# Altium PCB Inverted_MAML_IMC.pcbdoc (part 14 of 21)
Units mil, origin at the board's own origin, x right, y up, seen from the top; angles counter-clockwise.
Board outline 7677.1 x 6771.6 mil, 6 copper layers (Top Layer, Inner1, Inner2, Inner3, Inner4, Bottom Layer), stack 60.7 mil thick; 2732 components, 1531 nets, 7765 pads, 3705 vias.
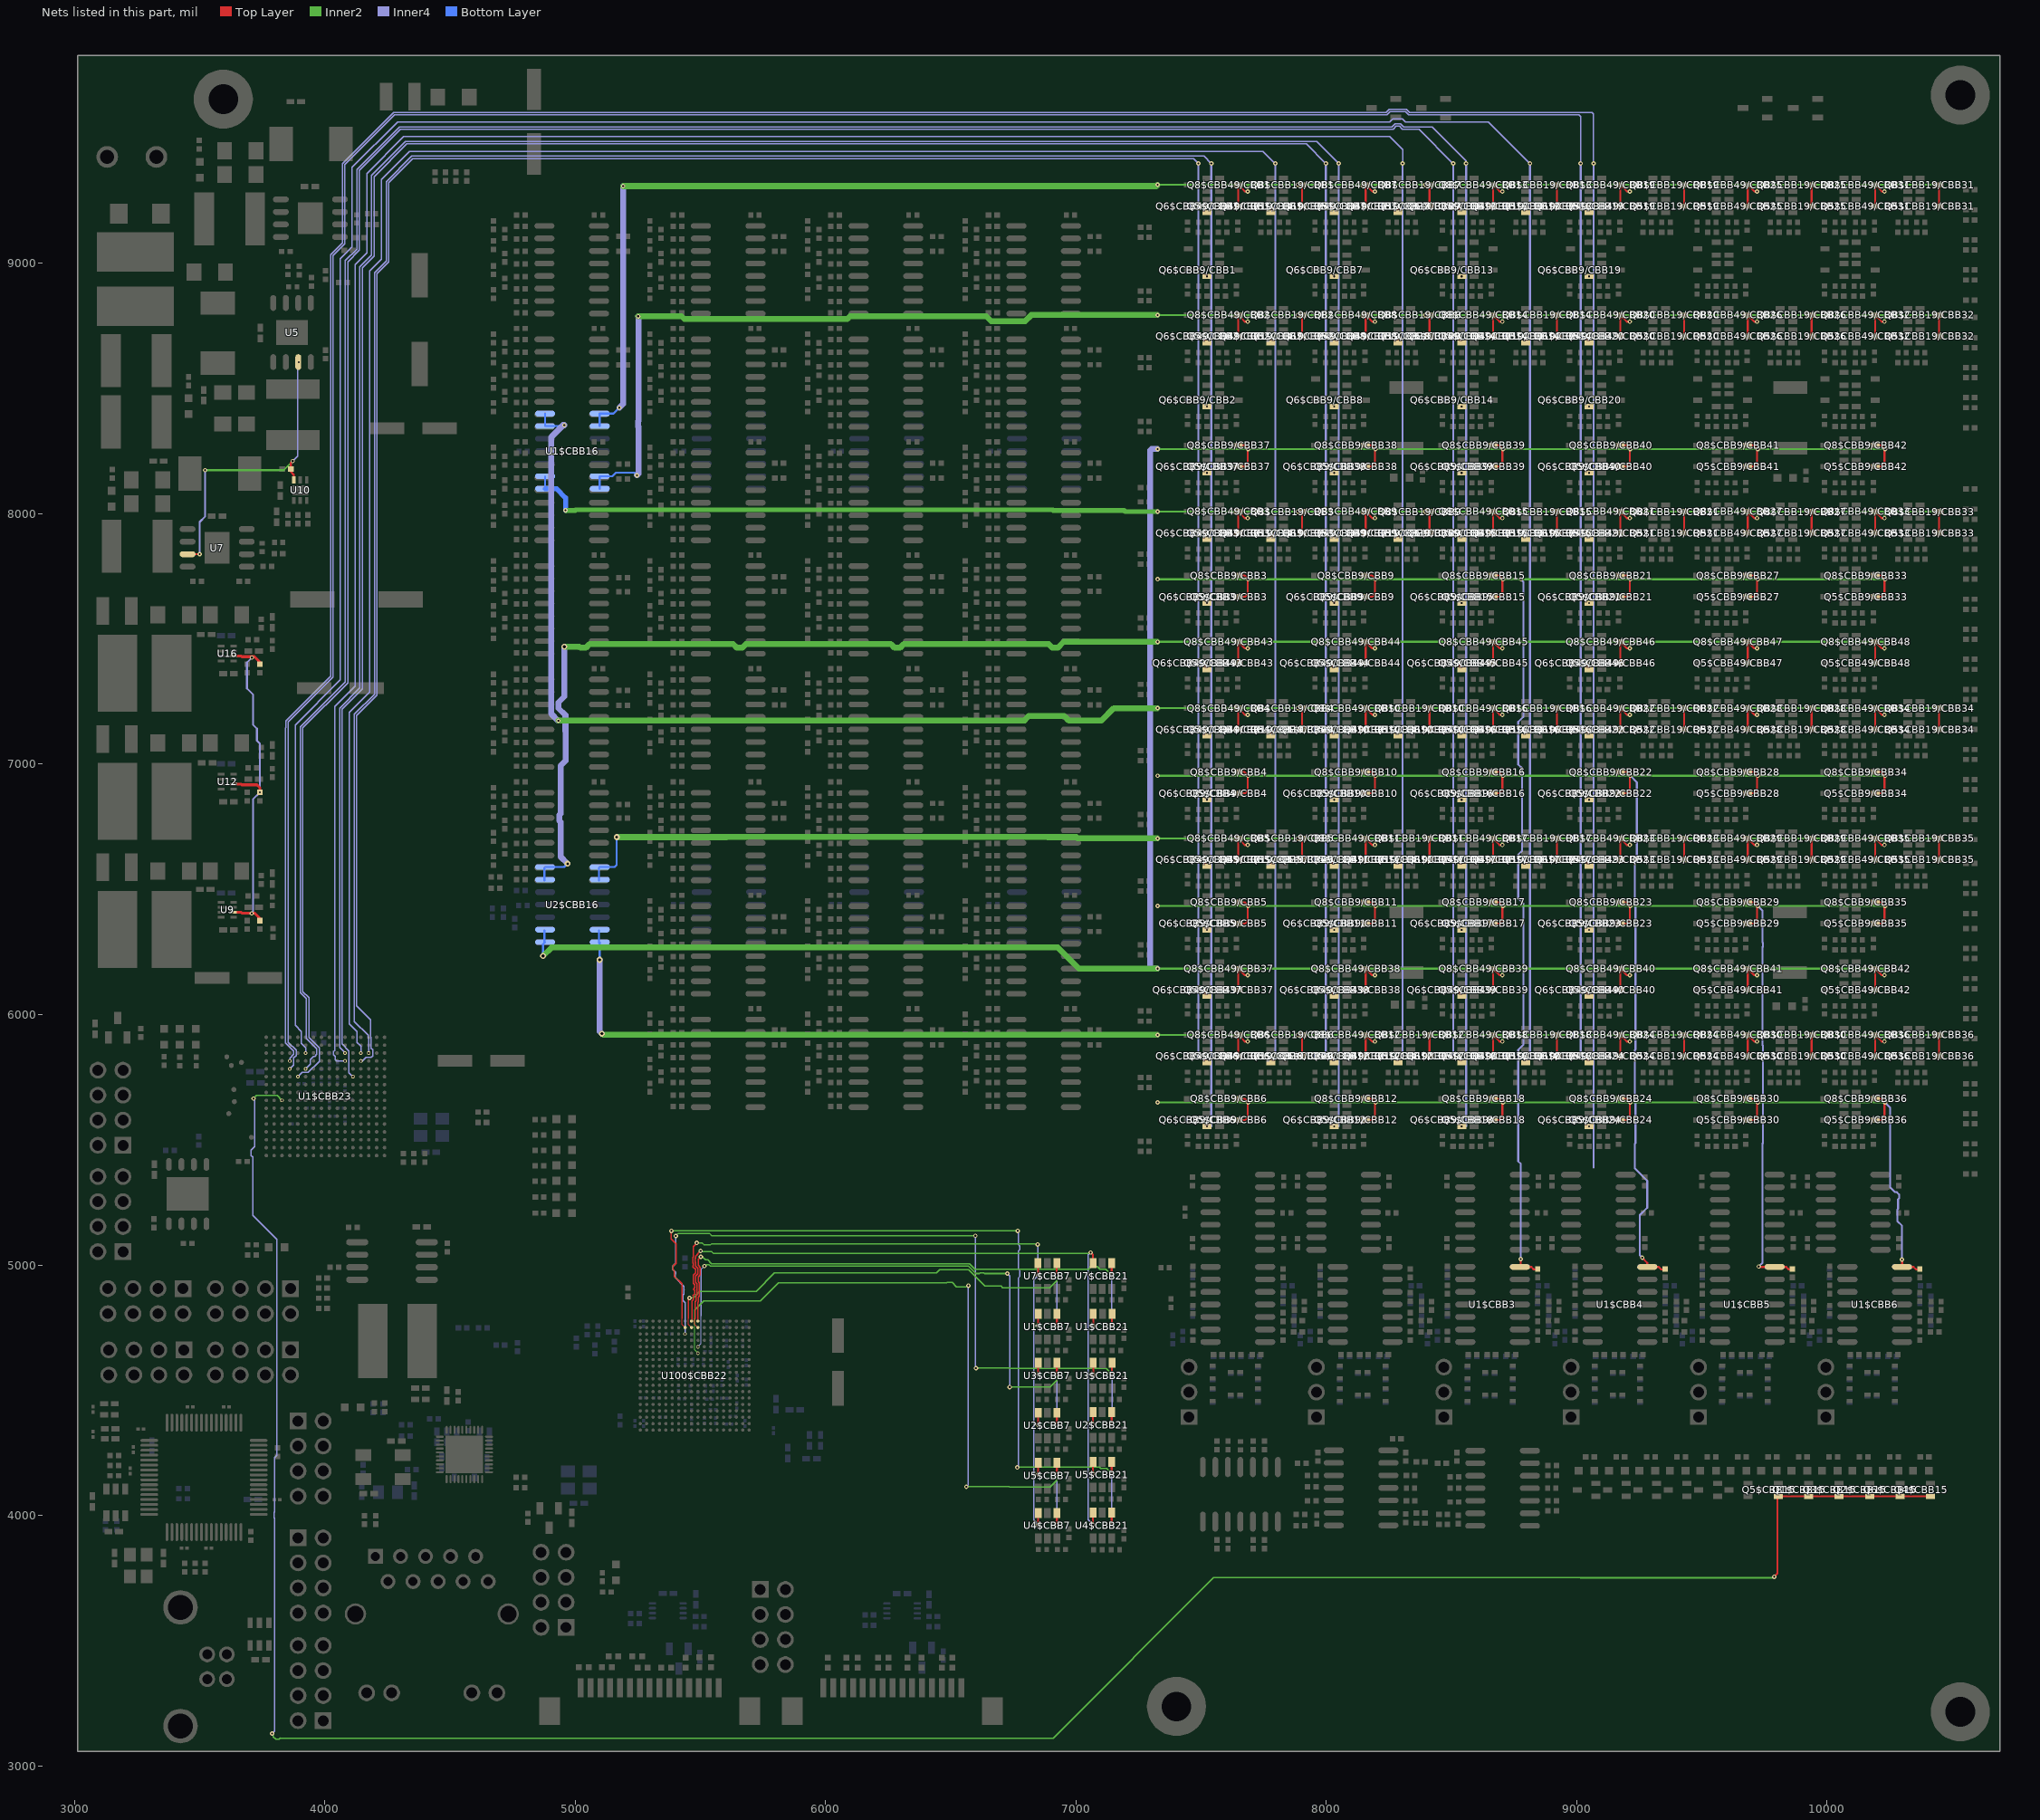
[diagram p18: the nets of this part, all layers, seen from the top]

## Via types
v1: diameter 17.7, hole 7.9, Top Layer to Bottom Layer, 3373 vias
v2: diameter 13.8, hole 7.9, Top Layer to Bottom Layer, 287 vias
v3: diameter 23.6, hole 11.8, Top Layer to Bottom Layer, 45 vias

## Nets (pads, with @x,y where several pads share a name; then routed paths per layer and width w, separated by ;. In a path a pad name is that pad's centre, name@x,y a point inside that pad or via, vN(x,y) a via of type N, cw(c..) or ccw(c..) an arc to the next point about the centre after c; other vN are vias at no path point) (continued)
ACT(4)_D_ROW3: Q5$CBB9/CBB3.3 Q5$CBB9/CBB9.3 Q5$CBB9/CBB15.3 Q5$CBB9/CBB21.3 Q5$CBB9/CBB27.3 Q5$CBB9/CBB33.3 Q8$CBB9/CBB3.3 Q8$CBB9/CBB9.3 Q8$CBB9/CBB15.3 Q8$CBB9/CBB21.3 Q8$CBB9/CBB27.3 Q8$CBB9/CBB33.3 R14$CBB3.2 U1$CBB3.14 | length 6663.9
  Top Layer w7.9: Q5$CBB9/CBB3.3@7648.6,7668.7 7676.2,7668.7 7686.2,7678.7 v1@7686.2,7738.7 ; Q8$CBB9/CBB3.3@7648.6,7753.7 7673.7,7753.7 v1(7688.7,7738.7) ; Q5$CBB9/CBB9.3@8157.3,7668.7 8184.9,7668.7 8194.9,7678.7 v1@8194.9,7738.7 ; Q8$CBB9/CBB9.3@8157.3,7753.7 8182.4,7753.7 v1(8197.4,7738.7) ; Q5$CBB9/CBB15.3@8666,7668.7 8693.6,7668.7 8703.6,7678.7 v1@8703.6,7738.7 ; Q8$CBB9/CBB15.3@8666,7753.7 8691.1,7753.7 v1(8706.1,7738.7) ; v1(8777.1,5023.7) 8777.1,4995.7 U1$CBB3.14@8773.5,4992.2 8819.5,4992.2 8829.5,4982.2 8842.5,4982.2 R14$CBB3.2@8844.5,4984.2 ; Q5$CBB9/CBB21.3@9174.7,7668.7 9202.3,7668.7 9212.3,7678.7 v1@9212.3,7738.7 ; Q8$CBB9/CBB21.3@9174.7,7753.7 9199.8,7753.7 v1(9214.8,7738.7) ; Q5$CBB9/CBB27.3@9683.4,7668.7 9711,7668.7 9721,7678.7 v1@9721,7738.7 ; Q8$CBB9/CBB27.3@9683.4,7753.7 9708.5,7753.7 v1(9723.5,7738.7) ; Q5$CBB9/CBB33.3@10192.1,7668.7 10219.7,7668.7 10229.7,7678.7 v1@10229.7,7738.7 ; Q8$CBB9/CBB33.3@10192.1,7753.7 10217.2,7753.7 v1(10232.2,7738.7)
  Inner2 w7.9: v1(7326.2,7738.7) v1(7688.7,7738.7) v1(8197.4,7738.7) v1(8706.1,7738.7) v1(8777.6,7738.7) v1(9214.8,7738.7) v1(9723.5,7738.7) v1(10232.2,7738.7)
  Inner4 w7.9: v1(8777.1,5023.7) 8777.1,5403.7 8767.1,5413.7 8767.1,5858.7 8787.1,5878.7 8787.1,6443.7 8767.1,6463.7 8767.1,6638.7 8782.1,6653.7 8782.1,6983.7 8767.1,6998.7 8767.1,7168.7 8787.1,7188.7 8787.1,7728.7 v1@8777.1,7738.7
ACT(4)_D_ROW4: Q5$CBB9/CBB4.3 Q5$CBB9/CBB10.3 Q5$CBB9/CBB16.3 Q5$CBB9/CBB22.3 Q5$CBB9/CBB28.3 Q5$CBB9/CBB34.3 Q8$CBB9/CBB4.3 Q8$CBB9/CBB10.3 Q8$CBB9/CBB16.3 Q8$CBB9/CBB22.3 Q8$CBB9/CBB28.3 Q8$CBB9/CBB34.3 R14$CBB4.2 U1$CBB4.14 | length 5896.7
  Top Layer w7.9: Q5$CBB9/CBB4.3@7648.6,6883.7 7676.2,6883.7 7686.2,6893.7 v1@7686.2,6953.7 ; Q8$CBB9/CBB4.3@7648.6,6968.7 7673.7,6968.7 v1(7688.7,6953.7) ; Q5$CBB9/CBB10.3@8157.3,6883.7 8184.9,6883.7 8194.9,6893.7 v1@8194.9,6953.7 ; Q8$CBB9/CBB10.3@8157.3,6968.7 8182.4,6968.7 v1(8197.4,6953.7) ; Q5$CBB9/CBB16.3@8666,6883.7 8693.6,6883.7 8703.6,6893.7 v1@8703.6,6953.7 ; Q8$CBB9/CBB16.3@8666,6968.7 8691.1,6968.7 v1(8706.1,6953.7) ; Q5$CBB9/CBB22.3@9174.7,6883.7 9202.3,6883.7 9212.3,6893.7 v1@9212.3,6953.7 ; Q8$CBB9/CBB22.3@9174.7,6968.7 9199.8,6968.7 v1(9214.8,6953.7) ; v1(9262.1,5028.7) 9282.3,5008.6 U1$CBB4.14@9282.3,4992.2 9328.2,4992.2 9338.2,4982.2 9351.2,4982.2 R14$CBB4.2@9353.2,4984.2 ; Q5$CBB9/CBB28.3@9683.4,6883.7 9711,6883.7 9721,6893.7 v1@9721,6953.7 ; Q8$CBB9/CBB28.3@9683.4,6968.7 9708.5,6968.7 v1(9723.5,6953.7) ; Q5$CBB9/CBB34.3@10192.1,6883.7 10219.7,6883.7 10229.7,6893.7 v1@10229.7,6953.7 ; Q8$CBB9/CBB34.3@10192.1,6968.7 10217.2,6968.7 v1(10232.2,6953.7)
  Inner2 w7.9: v1(7326.2,6953.7) v1(7688.7,6953.7) v1(8197.4,6953.7) v1(8706.1,6953.7) v1(9214.8,6953.7) v1(9723.5,6953.7) v1(10232.2,6953.7)
  Inner4 w7.9: v1(9214.8,6953.7) 9240.7,6927.8 9240.7,6632.3 9232.1,6623.7 9232.1,6441.5 9235.1,6438.6 9235.1,5861.4 9232.1,5858.4 9232.1,5656.5 9235.1,5653.6 9235.1,5486.4 9232.1,5483.4 9232.1,5386.5 9282.1,5336.5 9282.1,5228.7 9252.1,5198.7 9252.1,5038.7 v1(9262.1,5028.7)
ACT(4)_D_ROW5: Q5$CBB9/CBB5.3 Q5$CBB9/CBB11.3 Q5$CBB9/CBB17.3 Q5$CBB9/CBB23.3 Q5$CBB9/CBB29.3 Q5$CBB9/CBB35.3 Q8$CBB9/CBB5.3 Q8$CBB9/CBB11.3 Q8$CBB9/CBB17.3 Q8$CBB9/CBB23.3 Q8$CBB9/CBB29.3 Q8$CBB9/CBB35.3 R14$CBB5.2 U1$CBB5.14 | length 5391.4
  Top Layer w7.9: Q5$CBB9/CBB5.3@7648.6,6363.7 7676.2,6363.7 7686.2,6373.7 v1@7686.2,6433.7 ; Q8$CBB9/CBB5.3@7648.6,6448.7 7673.7,6448.7 v1(7688.7,6433.7) ; Q5$CBB9/CBB11.3@8157.3,6363.7 8184.9,6363.7 8194.9,6373.7 v1@8194.9,6433.7 ; Q8$CBB9/CBB11.3@8157.3,6448.7 8182.4,6448.7 v1(8197.4,6433.7) ; Q5$CBB9/CBB17.3@8666,6363.7 8693.6,6363.7 8703.6,6373.7 v1@8703.6,6433.7 ; Q8$CBB9/CBB17.3@8666,6448.7 8691.1,6448.7 v1(8706.1,6433.7) ; Q5$CBB9/CBB23.3@9174.7,6363.7 9202.3,6363.7 9212.3,6373.7 v1@9212.3,6433.7 ; Q8$CBB9/CBB23.3@9174.7,6448.7 9199.8,6448.7 v1(9214.8,6433.7) ; Q5$CBB9/CBB29.3@9683.4,6363.7 9711,6363.7 9721,6373.7 v1@9721,6433.7 ; Q8$CBB9/CBB29.3@9683.4,6448.7 9708.5,6448.7 v1(9723.5,6433.7) ; v1(9727.1,4993.7) 9728.7,4992.2 U1$CBB5.14@9791,4992.2 9836.9,4992.2 9846.9,4982.2 9859.9,4982.2 R14$CBB5.2@9861.9,4984.2 ; Q5$CBB9/CBB35.3@10192.1,6363.7 10219.7,6363.7 10229.7,6373.7 v1@10229.7,6433.7 ; Q8$CBB9/CBB35.3@10192.1,6448.7 10217.2,6448.7 v1(10232.2,6433.7)
  Inner2 w7.9: v1(7326.2,6433.7) v1(7688.7,6433.7) v1(8197.4,6433.7) v1(8706.1,6433.7) v1(9214.8,6433.7) v1(9723.5,6433.7) v1(10232.2,6433.7)
  Inner4 w7.9: v1(9723.5,6433.7) 9742.1,6415.1 9742.1,6287.8 9743.8,6286.1 9743.8,6271.4 9742.1,6269.7 9742.1,5877.8 9743.8,5876.1 9743.8,5486.4 9742.1,5484.7 9742.1,5008.7 v1(9727.1,4993.7)
ACT(4)_D_ROW6: Q5$CBB9/CBB6.3 Q5$CBB9/CBB12.3 Q5$CBB9/CBB18.3 Q5$CBB9/CBB24.3 Q5$CBB9/CBB30.3 Q5$CBB9/CBB36.3 Q8$CBB9/CBB6.3 Q8$CBB9/CBB12.3 Q8$CBB9/CBB18.3 Q8$CBB9/CBB24.3 Q8$CBB9/CBB30.3 Q8$CBB9/CBB36.3 R14$CBB6.2 U1$CBB6.14 | length 4563.1
  Top Layer w7.9: Q5$CBB9/CBB6.3@7648.6,5578.7 7676.2,5578.7 7686.2,5588.7 v1@7686.2,5648.7 ; Q8$CBB9/CBB6.3@7648.6,5663.7 7673.7,5663.7 v1(7688.7,5648.7) ; Q5$CBB9/CBB12.3@8157.3,5578.7 8184.9,5578.7 8194.9,5588.7 v1@8194.9,5648.7 ; Q8$CBB9/CBB12.3@8157.3,5663.7 8182.4,5663.7 v1(8197.4,5648.7) ; Q5$CBB9/CBB18.3@8666,5578.7 8693.6,5578.7 8703.6,5588.7 v1@8703.6,5648.7 ; Q8$CBB9/CBB18.3@8666,5663.7 8691.1,5663.7 v1(8706.1,5648.7) ; Q5$CBB9/CBB24.3@9174.7,5578.7 9202.3,5578.7 9212.3,5588.7 v1@9212.3,5648.7 ; Q8$CBB9/CBB24.3@9174.7,5663.7 9199.8,5663.7 v1(9214.8,5648.7) ; Q5$CBB9/CBB30.3@9683.4,5578.7 9711,5578.7 9721,5588.7 v1@9721,5648.7 ; Q8$CBB9/CBB30.3@9683.4,5663.7 9708.5,5663.7 v1(9723.5,5648.7) ; Q5$CBB9/CBB36.3@10192.1,5578.7 10219.7,5578.7 10229.7,5588.7 v1@10229.7,5648.7 ; Q8$CBB9/CBB36.3@10192.1,5663.7 10217.2,5663.7 v1(10232.2,5648.7) ; v1(10299.5,5021.7) 10299.7,5021.6 U1$CBB6.14@10299.7,4992.2 10345.6,4992.2 10355.6,4982.2 10368.6,4982.2 R14$CBB6.2@10370.6,4984.2
  Inner2 w7.9: v1(7326.2,5648.7) v1(7688.7,5648.7) v1(8197.4,5648.7) v1(8706.1,5648.7) v1(9214.8,5648.7) v1(9723.5,5648.7) v1(10232.2,5648.7)
  Inner4 w7.9: v1(10232.2,5648.7) 10252.1,5628.8 10252.1,5501.5 10252.5,5501.1 10252.5,5486.4 10252.1,5486 10252.1,5309.9 10270.4,5291.6 10277.4,5291.6 10287.8,5281.2 10287.8,5266.4 10283.8,5262.4 10283.8,5224.3 10280.6,5221 10280.6,5175.2 10299.6,5156.1 v1@10299.6,5023.7
ADC(45)_CONV: U1$CBB7.6 U2$CBB7.6 U3$CBB7.6 U4$CBB7.6 U5$CBB7.6 U7$CBB7.6 U100$CBB22.V10 | length 3202.2
  Top Layer w4.7: U100$CBB22.V10@5465.1,4775.7 5467.2,4777.8 5467.2,4855.7 5473.2,4861.7 5473.2,4875.1 5470.9,4877.5 5477.2,4883.8 5477.2,4897.2 5471.9,4902.6 5477.2,4907.9 5477.2,4921.3 5472.5,4926 5472.5,4944.9 5472,4945.3 5472,4960.3 5480.7,4969 5480.7,4982.4 5471.2,4991.9 5470,4991.9 5470,4994.9 5472.5,4997.4 5472.5,5006.7 5470.7,5008.5 5470.7,5030 5472.5,5031.8 5472.5,5074.2 v1(5486.4,5088.1)
  Top Layer w7.9: U7$CBB7.6@6849.2,5006.9 6849.2,4959.7 v1(6849.4,4959.5) ; U4$CBB7.6@6849.7,4009.9 6849.7,3962.7 v1(6849.9,3962.5) ; U5$CBB7.6@6849.7,4209.9 6849.7,4162.7 v1(6849.9,4162.5) ; U2$CBB7.6@6849.7,4409.9 6849.7,4362.7 v1(6849.9,4362.5) ; U3$CBB7.6@6849.7,4609.9 6849.7,4562.7 v1(6849.9,4562.5) ; U1$CBB7.6@6849.7,4804.9 6849.7,4757.7 v1(6849.9,4757.5)
  Inner2 w5.5: v1(5486.4,5088.1) 5507.9,5088.1 5514.9,5081.1 5542,5081.1 5545.6,5084.7 6845.4,5084.7 v1(6847.9,5082.1)
  Inner4 w4.7: 6831.7,4162.4 6831.9,4162.4 ; v1(6849.4,4959.5) 6831.9,4941.9 6831.9,4757.2 ; v1@6849.7,4162.7 6849.4,4162.4 6831.9,4162.4 ; v1(6849.9,3962.5) 6831.9,3980.6 6831.9,4162.4 ; v1(6849.9,4362.5) 6849.6,4362.2 6831.9,4362.2 ; v1(6849.9,4562.5) 6849.6,4562.2 6831.9,4562.2 ; v1(6849.9,4757.5) 6849.6,4757.2 6831.9,4757.2 ; 6831.9,4162.4 6831.9,4362.2 ; 6831.9,4362.2 6831.9,4562.2 ; 6831.9,4562.2 6831.9,4757.2
  Inner4 w5.5: v1(6847.9,5082.1) 6847.9,4960.9 v1(6849.4,4959.5)
ADC(45)_SCK_1_2: U1$CBB7.4 U7$CBB7.4 U100$CBB22.U10 | length 2000.1
  Top Layer w4.3: 5452.1,4785.2 5452.5,4784.8 5452.5,4762.7 U100$CBB22.U10@5465.1,4750.1
  Top Layer w4.7: 5452.1,4785.2 5452.1,4863.6 v1(5457,4868.4)
  Top Layer w7.9: U7$CBB7.4@6924,5006.9 6924,4959.7 v1(6924.2,4959.5) ; U1$CBB7.4@6924.5,4804.9 6924.5,4757.7 v1(6924.7,4757.5)
  Inner2 w4.7: v1(5457,4868.4) 5471.6,4868.4 5498.5,4895.2 5723.3,4895.2 5796.2,4968.1 6443.1,4968.1 6456.1,4981.1 6571.2,4981.1 6636.1,4916.2 6692.3,4916.2 6692.8,4915.6 6702,4915.6 6708.2,4909.4 6896.1,4909.4 6924.2,4937.5 v1(6924.2,4959.5)
  Inner4 w4.7: v1(6924.2,4959.5) 6924.2,4758.1 v1(6924.7,4757.5)
ADC(45)_SCK_3_4: U2$CBB7.4 U3$CBB7.4 U100$CBB22.P9 | length 2538.3
  Top Layer w7.9: U2$CBB7.4@6924.5,4409.9 6924.5,4362.7 v1(6924.7,4362.5) ; U3$CBB7.4@6924.5,4609.9 6924.5,4562.7 v1(6924.7,4562.5)
  Inner2 w4.7: v1(6736,4512.5) 6896.6,4512.5 6924.7,4540.6 v1(6924.7,4562.5)
  Inner2 w5.5: v1(5516.4,4995.6) 5521.1,5000.4 5535.6,5000.4 5541.1,4994.8 6571.7,4994.8 6600.9,4965.7 6615.6,4965.7 6618.2,4968.2 6631.9,4968.2 6634.5,4965.7 v1(6725.8,4965.7)
  Inner4 w3.9: v2(5490.7,4673.3) 5503.5,4686.1 5503.5,4796.2
  Inner4 w4.7: 5503.5,4796.2 5503.5,4843.2 ; v1(6924.7,4562.5) 6924.7,4361.1 v1@6925.3,4360.6
  Inner4 w5.5: 5503.5,4843.2 5502.6,4844 5502.6,4981.8 v1(5516.4,4995.6) ; v1(6725.8,4965.7) 6736,4955.5 v1(6736,4512.5)
ADC(45)_SCK_5_6: U4$CBB7.4 U5$CBB7.4 U100$CBB22.N9 | length 2824.2
  Top Layer w7.9: U4$CBB7.4@6924.5,4009.9 6924.5,3962.7 v1(6924.7,3962.5) ; U5$CBB7.4@6924.5,4209.9 6924.5,4162.7 v1(6924.7,4162.5)
  Inner2 w3.9: 5477.9,4796.2 5477.9,4660.6 v2(5490.7,4647.8)
  Inner2 w4.7: 5477.9,4796.2 5477.9,4819.6 5514.6,4856.3 5739.5,4856.3 5812.3,4929.2 6485.3,4929.2 6485.8,4929.7 6507.3,4929.7 6523.8,4913.1 6566.5,4913.1 v1(6570.8,4917.5) ; 6736,4112.5 6896.6,4112.5 6924.7,4140.6 v1(6924.7,4162.5)
  Inner2 w5.5: v1(6562.8,4114.3) 6734.2,4114.3 6736,4112.5
  Inner4 w4.7: v1(6924.7,4162.5) 6924.7,3961.1 v1@6925.3,3960.6
  Inner4 w5.5: v1(6562.8,4114.3) 6570.8,4122.4 v1(6570.8,4917.5)
ADC(49)_CONV: U1$CBB21.6 U2$CBB21.6 U3$CBB21.6 U4$CBB21.6 U5$CBB21.6 U7$CBB21.6 U100$CBB22.U9 | length 3362.5
  Top Layer w4.3: 5477.7,4785.2 5478.1,4784.8 5478.1,4762.7 U100$CBB22.U9@5490.7,4750.1
  Top Layer w4.7: 5477.7,4785.2 5478.9,4786.3 5478.9,4853.6 5482.9,4857.7 5482.9,4875.7 5486.9,4879.8 5486.9,4901.3 5485.6,4902.6 5486.9,4903.9 5486.9,4925.3 5482.2,4930.1 5482.2,4948.9 5481.8,4949.3 5481.8,4956.3 5490.4,4965 5490.4,4986.5 5482.2,4994.7 5482.2,5010.7 5480.4,5012.6 5480.4,5026 5482.2,5027.8 5482.2,5035.6 5486.4,5039.8 5486.4,5041.4 5495.9,5050.9 5496.2,5050.9 v1(5501.4,5056.2)
  Top Layer w7.9: v1(7058.7,5049.8) 7068.5,5040 U7$CBB21.6@7068.5,5006.9 ; U4$CBB21.6@7068.5,4010.7 7068.5,3963.4 v1(7068.7,3963.3) ; U5$CBB21.6@7068.5,4213.9 7068.5,4166.2 v1(7068.7,4166) ; U2$CBB21.6@7068.5,4412.2 7068.5,4364.9 v1(7068.7,4364.7) ; U3$CBB21.6@7069.7,4609.9 7069.7,4562.7 v1(7069.9,4562.5) ; U1$CBB21.6@7069.7,4804.9 7069.7,4757.7 v1(7069.9,4757.5)
  Inner2 w5.5: v1(5501.4,5056.2) 5504.7,5053 5546.1,5053 5553.1,5046 7054.8,5046 v1(7058.7,5049.8)
  Inner4 w4.7: 7049.7,4757.3 7050.1,4757.7 v1@7069.7,4757.7 ; 7049.9,4562.1 7050.3,4562.5 v1(7069.9,4562.5) ; v1(7058.7,5049.8) 7048.7,5039.9 7048.7,4364.3 ; v1(7068.7,3963.3) 7048.7,3983.2 7048.7,4166.1 ; v1(7068.7,4166) 7048.8,4166 7048.7,4166.1 ; v1(7068.7,4364.7) 7049.1,4364.7 7048.7,4364.3 ; 7048.7,4166.1 7048.7,4364.3
ADC(49)_SCK_1_2: U1$CBB21.4 U7$CBB21.4 U100$CBB22.V9 | length 2250.1
  Top Layer w4.7: U100$CBB22.V9@5490.7,4775.7 5490.7,4821.3 5490.6,4821.4 5490.6,4851.6 5492.6,4853.6 5492.6,4871.7 5496.7,4875.7 5496.7,4929.4 5491.9,4934.1 5491.9,4952.7 5500.2,4960.9 5500.2,4990.5 5491.9,4998.7 5491.9,5021.8 v1(5502.6,5032.5)
  Top Layer w7.9: U7$CBB21.4@7143.3,5006.9 7143.3,4959.7 v1(7143.5,4959.5) ; U1$CBB21.4@7144.5,4804.9 7144.5,4757.7 v1(7144.7,4757.5)
  Inner2 w4.7: v1(5502.6,5032.5) 5509.4,5032.5 5521.8,5020.2 5530.4,5020.2 5545.6,5005 6575.9,5005 6597.9,4982.9 7050.2,4982.9 7060.7,4993.5 7085.8,4993.5 7096.4,4982.9 7120,4982.9 v1@7143.7,4959.3
  Inner4 w4.7: v1@7143.7,4959.3 7143.7,4757.9 v1@7144.2,4757.3
ADC(49)_SCK_3_4: U2$CBB21.4 U3$CBB21.4 U100$CBB22.T11 | length 3008.4
  Top Layer w7.9: U2$CBB21.4@7143.3,4412.2 7143.3,4364.9 v1(7143.5,4364.7) ; U3$CBB21.4@7144.5,4609.9 7144.5,4562.7 v1(7144.7,4562.5)
  Inner2 w4.7: 6737.5,4586.2 7121.1,4586.2 v1(7144.7,4562.5)
  Inner2 w5.5: v1(5402.2,5116.3) 5412.3,5126.3 5536.2,5126.3 5545.7,5116.8 v1(6598.9,5116.8) ; v1(6600.9,4588.2) 6735.5,4588.2 6737.5,4586.2
  Inner4 w4.7: v1(5402.2,5116.3) 5402.2,5004.3 5399.7,5004.3 5390.2,4994.8 5390.2,4981.4 5399.7,4971.9 5402.2,4971.9 5402.2,4962.7 5399.9,4960.3 5399.9,4949.9 5435,4914.8 5435,4903.9 5436.3,4902.6 5435,4901.3 5435,4883.2 5431,4879.2 5431,4857.7 5439.5,4849.2 v2(5439.5,4724.5) ; v1(7143.5,4364.7) 7144.7,4366 v1(7144.7,4562.5)
  Inner4 w5.5: v1(6598.9,5116.8) 6598.9,4590.2 v1(6600.9,4588.2)
ADC(49)_SCK_5_6: U4$CBB21.4 U5$CBB21.4 U100$CBB22.U11 | length 3451.8
  Top Layer w4.3: 5426.5,4785.2 5426.9,4784.8 5426.9,4762.7 U100$CBB22.U11@5439.5,4750.1
  Top Layer w4.7: v1(5384.2,5136.3) 5384.2,5104.2 5403.9,5084.4 5403.9,5004.3 5399.7,5004.3 5390.2,4994.8 5390.2,4981.4 5396.7,4974.9 5396.7,4954.8 5426.5,4925 5426.5,4785.2
  Top Layer w7.9: U4$CBB21.4@7143.3,4010.7 7143.3,3963.4 v1(7143.5,3963.3) ; U5$CBB21.4@7143.3,4213.9 7143.3,4166.7 v1(7143.5,4166.5)
  Inner2 w4.7: v1@6767.1,4192.7 7094.2,4192.7 7100.3,4186.6 7123.4,4186.6 v1(7143.5,4166.5)
  Inner2 w5.5: v1(5384.2,5136.3) 5384.6,5136.8 6767.1,5136.8 v1(6767.6,5136.3) ; v1(6765.6,4191.2) v1@6767.1,4192.7
  Inner4 w4.7: v1(7143.5,4166.5) 7143.5,3965.1 v1@7144,3964.6
  Inner4 w5.5: v1(6765.6,4191.2) 6770.1,4195.7 6770.1,4947.9 6776.7,4954.4 6776.7,4976.9 6770.1,4983.5 6770.1,5055.1 6776.2,5061.2 6776.2,5075 6770.1,5081.1 6770.1,5133.9 v1(6767.6,5136.3)
COMP_LED_ON: Q1$CBB15.1 Q2$CBB15.1 Q3$CBB15.1 Q4$CBB15.1 Q5$CBB15.1 Q6$CBB15.1 U1$CBB23.J3 | length 9941.2
  Top Layer w7.9: v1(9789.1,3754.9) 9801.5,3767.3 9801.5,4068.2 9809.4,4076.1 Q1$CBB15.1@9926.9,4076.1 Q3$CBB15.1@10048.4,4076.1 Q2$CBB15.1@10169.9,4076.1 Q6$CBB15.1@10291.3,4076.1 Q4$CBB15.1@10412.8,4076.1
  Inner2 w4.7: v1(3715.6,5664.6) 3727.5,5676.5 3810.6,5676.5 v2(3829.6,5657.4) ; v1(3789.9,3128.5) 3790.6,3129.2 3795.2,3129.2 3795.2,3115.7 3804.7,3106.2 3818.1,3106.2 3823.2,3111.3 3824.1,3110.4 6910.2,3110.4 7550.7,3750.9 9016.4,3750.9
  Inner2 w7.9: 9016.4,3750.9 9785.1,3750.9 v1(9789.1,3754.9)
  Inner4 w4.7: v1(3715.6,5664.6) 3719.6,5660.6 3719.6,5472.6 3706.1,5459 3706.1,5437.5 3712.6,5431 3712.6,5198.2 3719.6,5191.2 3719.6,5190.9 3808.3,5102.2 3808.3,4239.1 3800,4230.8 3800,4014.5 3798.1,4012.6 3798.1,3991.1 3800,3989.3 3800,3138.5 v1(3789.9,3128.5)
DAC2_D_ROW1: Q5$CBB19/CBB1.3 Q5$CBB19/CBB7.3 Q5$CBB19/CBB13.3 Q5$CBB19/CBB19.3 Q5$CBB19/CBB25.3 Q5$CBB19/CBB31.3 Q5$CBB49/CBB1.3 Q5$CBB49/CBB7.3 Q5$CBB49/CBB13.3 Q5$CBB49/CBB19.3 Q5$CBB49/CBB25.3 Q5$CBB49/CBB31.3 Q8$CBB19/CBB1.3 Q8$CBB19/CBB7.3 Q8$CBB19/CBB13.3 Q8$CBB19/CBB19.3 Q8$CBB19/CBB25.3 Q8$CBB19/CBB31.3 Q8$CBB49/CBB1.3 Q8$CBB49/CBB7.3 Q8$CBB49/CBB13.3 Q8$CBB49/CBB19.3 Q8$CBB49/CBB25.3 Q8$CBB49/CBB31.3 U1$CBB16.1 U1$CBB16.2 | length 7938.7
  Top Layer w7.9: Q5$CBB49/CBB1.3@7648.6,9228.7 Q8$CBB49/CBB1.3@7648.6,9313.7 7674.9,9287.4 v1(7686,9287.4) ; Q5$CBB19/CBB1.3@7903.6,9228.7 Q8$CBB19/CBB1.3@7903.6,9313.7 ; Q5$CBB49/CBB7.3@8157.3,9228.7 Q8$CBB49/CBB7.3@8157.3,9313.7 8183.6,9287.4 v1(8194.7,9287.4) ; Q5$CBB19/CBB7.3@8412.3,9228.7 Q8$CBB19/CBB7.3@8412.3,9313.7 ; Q5$CBB49/CBB13.3@8666,9228.7 Q8$CBB49/CBB13.3@8666,9313.7 8692.3,9287.4 v1(8703.4,9287.4) ; Q5$CBB19/CBB13.3@8921,9228.7 Q8$CBB19/CBB13.3@8921,9313.7 ; Q5$CBB49/CBB19.3@9174.7,9228.7 Q8$CBB49/CBB19.3@9174.7,9313.7 9201,9287.4 v1(9212.1,9287.4) ; Q5$CBB19/CBB19.3@9429.7,9228.7 Q8$CBB19/CBB19.3@9429.7,9313.7 ; Q5$CBB49/CBB25.3@9683.4,9228.7 Q8$CBB49/CBB25.3@9683.4,9313.7 9709.7,9287.4 v1(9720.8,9287.4) ; Q5$CBB19/CBB25.3@9938.4,9228.7 Q8$CBB19/CBB25.3@9938.4,9313.7 ; Q5$CBB49/CBB31.3@10192.1,9228.7 Q8$CBB49/CBB31.3@10192.1,9313.7 10218.4,9287.4 v1(10229.5,9287.4) ; Q5$CBB19/CBB31.3@10447.1,9228.7 Q8$CBB19/CBB31.3@10447.1,9313.7
  Inner2 w7.9: v1(7326.2,9313.7) 7685.6,9313.7 ; v1(7686,9287.4) 7686,9313.4 7685.6,9313.7 ; v1(8194.7,9287.4) 8194.7,9313.4 8194.3,9313.7 ; v1(8703.4,9287.4) 8703.4,9313.3 8703,9313.7 v1(8903.6,9313.7) ; v1(9212.1,9287.4) 9212.1,9313.4 9211.7,9313.7 ; v1(9720.8,9287.4) 9720.8,9313.4 9720.4,9313.7 ; v1(10229.5,9287.4) 10229.5,9313.4 10229.1,9313.7 ; v1(10429.7,9313.7) 10229.1,9313.7 ; 7685.6,9313.7 v1(7886.2,9313.7) 8194.3,9313.7 ; 8194.3,9313.7 v1(8394.9,9313.7) v1(8903.6,9313.7) ; v1(8903.6,9313.7) 9211.7,9313.7 ; 9211.7,9313.7 v1(9412.3,9313.7) 9720.4,9313.7 ; 9720.4,9313.7 v1(9920.2,9313.7) 10229.1,9313.7
  Inner2 w23.6: v1(5192.1,9308.7) 7321.2,9308.7 v1(7326.2,9313.7)
  Inner4 w23.6: v1(5177.1,8423.7) 5192.1,8438.7 v1(5192.1,9308.7)
  Bottom Layer w7.9: U1$CBB16.2@5098.4,8350.1 U1$CBB16.1@5098.4,8400.1 5153.5,8400.1 v1(5177.1,8423.7)
DAC2_D_ROW2: Q5$CBB19/CBB2.3 Q5$CBB19/CBB8.3 Q5$CBB19/CBB14.3 Q5$CBB19/CBB20.3 Q5$CBB19/CBB26.3 Q5$CBB19/CBB32.3 Q5$CBB49/CBB2.3 Q5$CBB49/CBB8.3 Q5$CBB49/CBB14.3 Q5$CBB49/CBB20.3 Q5$CBB49/CBB26.3 Q5$CBB49/CBB32.3 Q8$CBB19/CBB2.3 Q8$CBB19/CBB8.3 Q8$CBB19/CBB14.3 Q8$CBB19/CBB20.3 Q8$CBB19/CBB26.3 Q8$CBB19/CBB32.3 Q8$CBB49/CBB2.3 Q8$CBB49/CBB8.3 Q8$CBB49/CBB14.3 Q8$CBB49/CBB20.3 Q8$CBB49/CBB26.3 Q8$CBB49/CBB32.3 U1$CBB16.6 U1$CBB16.7 | length 7722.5
  Top Layer w7.9: Q5$CBB49/CBB2.3@7648.6,8708.7 Q8$CBB49/CBB2.3@7648.6,8793.7 7674.9,8767.4 v1(7686,8767.4) ; Q5$CBB19/CBB2.3@7903.6,8708.7 Q8$CBB19/CBB2.3@7903.6,8793.7 ; Q5$CBB49/CBB8.3@8157.3,8708.7 Q8$CBB49/CBB8.3@8157.3,8793.7 8183.6,8767.4 v1(8194.7,8767.4) ; Q5$CBB19/CBB8.3@8412.3,8708.7 Q8$CBB19/CBB8.3@8412.3,8793.7 ; Q5$CBB49/CBB14.3@8666,8708.7 Q8$CBB49/CBB14.3@8666,8793.7 8692.3,8767.4 v1(8703.4,8767.4) ; Q5$CBB19/CBB14.3@8921,8708.7 Q8$CBB19/CBB14.3@8921,8793.7 ; Q5$CBB49/CBB20.3@9174.7,8708.7 Q8$CBB49/CBB20.3@9174.7,8793.7 9201,8767.4 v1(9212.1,8767.4) ; Q5$CBB19/CBB20.3@9429.7,8708.7 Q8$CBB19/CBB20.3@9429.7,8793.7 ; Q5$CBB49/CBB26.3@9683.4,8708.7 Q8$CBB49/CBB26.3@9683.4,8793.7 9709.7,8767.4 v1(9720.8,8767.4) ; Q5$CBB19/CBB26.3@9938.4,8708.7 Q8$CBB19/CBB26.3@9938.4,8793.7 ; Q5$CBB49/CBB32.3@10192.1,8708.7 Q8$CBB49/CBB32.3@10192.1,8793.7 10218.4,8767.4 v1(10229.5,8767.4) ; Q5$CBB19/CBB32.3@10447.1,8708.7 Q8$CBB19/CBB32.3@10447.1,8793.7
  Inner2 w7.9: v1(7326.2,8793.7) 7685.6,8793.7 ; v1(7686,8767.4) 7686,8793.4 7685.6,8793.7 ; v1(8194.7,8767.4) 8194.7,8793.4 8194.3,8793.7 ; v1(8703.4,8767.4) 8703.4,8793.3 8703,8793.7 v1(8903.6,8793.7) ; v1(9212.1,8767.4) 9212.1,8793.4 9211.7,8793.7 ; v1(9720.8,8767.4) 9720.8,8793.4 9720.4,8793.7 ; v1(10229.5,8767.4) 10229.5,8793.4 10229.1,8793.7 ; v1(10429.7,8793.7) 10229.1,8793.7 ; 7685.6,8793.7 v1(7886.2,8793.7) 8194.3,8793.7 ; 8194.3,8793.7 v1(8394.9,8793.7) v1(8903.6,8793.7) ; v1(8903.6,8793.7) 9211.7,8793.7 ; 9211.7,8793.7 v1(9412.3,8793.7) 9720.4,8793.7 ; 9720.4,8793.7 v1(9921,8793.7) 10229.1,8793.7
  Inner2 w23.6: v1(5252.1,8788.7) 5425.8,8788.7 5436.5,8778.1 6087.7,8778.1 6098.4,8788.7 6642.1,8788.7 6662.1,8768.7 6797.1,8768.7 6822.1,8793.7 v1(7326.2,8793.7)
  Inner4 w23.6: v1(5247.1,8153.7) 5253.7,8160.3 5253.7,8346.8 5252.1,8348.3 5252.1,8369.6 5253.7,8371.2 5253.7,8787.2 v1(5252.1,8788.7)
  Bottom Layer w7.9: U1$CBB16.7@5098.4,8100.1 U1$CBB16.6@5098.4,8150.1 5148.5,8150.1 5162.1,8163.7 5237.1,8163.7 v1(5247.1,8153.7)
DAC2_D_ROW3: Q5$CBB19/CBB3.3 Q5$CBB19/CBB9.3 Q5$CBB19/CBB15.3 Q5$CBB19/CBB21.3 Q5$CBB19/CBB27.3 Q5$CBB19/CBB33.3 Q5$CBB49/CBB3.3 Q5$CBB49/CBB9.3 Q5$CBB49/CBB15.3 Q5$CBB49/CBB21.3 Q5$CBB49/CBB27.3 Q5$CBB49/CBB33.3 Q8$CBB19/CBB3.3 Q8$CBB19/CBB9.3 Q8$CBB19/CBB15.3 Q8$CBB19/CBB21.3 Q8$CBB19/CBB27.3 Q8$CBB19/CBB33.3 Q8$CBB49/CBB3.3 Q8$CBB49/CBB9.3 Q8$CBB49/CBB15.3 Q8$CBB49/CBB21.3 Q8$CBB49/CBB27.3 Q8$CBB49/CBB33.3 U1$CBB16.8 U1$CBB16.9 | length 7337.7
  Top Layer w7.9: Q5$CBB49/CBB3.3@7648.6,7923.7 Q8$CBB49/CBB3.3@7648.6,8008.7 7674.9,7982.4 v1(7686,7982.4) ; Q5$CBB19/CBB3.3@7903.6,7923.7 Q8$CBB19/CBB3.3@7903.6,8008.7 ; Q5$CBB49/CBB9.3@8157.3,7923.7 Q8$CBB49/CBB9.3@8157.3,8008.7 8183.6,7982.4 v1(8194.7,7982.4) ; Q5$CBB19/CBB9.3@8412.3,7923.7 Q8$CBB19/CBB9.3@8412.3,8008.7 ; Q5$CBB49/CBB15.3@8666,7923.7 Q8$CBB49/CBB15.3@8666,8008.7 8692.3,7982.4 v1(8703.4,7982.4) ; Q5$CBB19/CBB15.3@8921,7923.7 Q8$CBB19/CBB15.3@8921,8008.7 ; Q5$CBB49/CBB21.3@9174.7,7923.7 Q8$CBB49/CBB21.3@9174.7,8008.7 9201,7982.4 v1(9212.1,7982.4) ; Q5$CBB19/CBB21.3@9429.7,7923.7 Q8$CBB19/CBB21.3@9429.7,8008.7 ; Q5$CBB49/CBB27.3@9683.4,7923.7 Q8$CBB49/CBB27.3@9683.4,8008.7 9709.7,7982.4 v1(9720.8,7982.4) ; Q5$CBB19/CBB27.3@9938.4,7923.7 Q8$CBB19/CBB27.3@9938.4,8008.7 ; Q5$CBB49/CBB33.3@10192.1,7923.7 Q8$CBB49/CBB33.3@10192.1,8008.7 10218.4,7982.4 v1(10229.5,7982.4) ; Q5$CBB19/CBB33.3@10447.1,7923.7 Q8$CBB19/CBB33.3@10447.1,8008.7
  Inner2 w7.9: v1(7326.2,8008.7) 7685.6,8008.7 ; v1(7686,7982.4) 7686,8008.4 7685.6,8008.7 ; v1(8194.7,7982.4) 8194.7,8008.4 8194.3,8008.7 ; v1(8703.4,7982.4) 8703.4,8008.3 8703,8008.7 v1(8903.6,8008.7) ; v1(9212.1,7982.4) 9212.1,8008.4 9211.7,8008.7 ; v1(9720.8,7982.4) 9720.8,8008.4 9720.4,8008.7 ; v1(10229.5,7982.4) 10229.5,8008.4 10229.1,8008.7 ; v1(10429.7,8008.7) 10229.1,8008.7 ; 7685.6,8008.7 v1(7886.2,8008.7) 8194.3,8008.7 ; 8194.3,8008.7 v1(8394.9,8008.7) v1(8903.6,8008.7) ; v1(8903.6,8008.7) 9211.7,8008.7 ; 9211.7,8008.7 v1(9412.3,8008.7) 9720.4,8008.7 ; 9720.4,8008.7 v1(9920.2,8008.7) 10229.1,8008.7
  Inner2 w19.7: v1(4962.1,8013.7) 5000.7,8013.7 5002.9,8015.9 6907.3,8015.9 6909.5,8013.7 7192.1,8013.7 7197.1,8008.7 v1(7326.2,8008.7)
  Bottom Layer w7.9: U1$CBB16.8@4880.3,8100.1 U1$CBB16.9@4880.3,8150.1
  Bottom Layer w19.7: U1$CBB16.8@4880.3,8100.1 4925.7,8100.1 4962.1,8063.7 v1(4962.1,8013.7)
DAC2_D_ROW4: Q5$CBB19/CBB4.3 Q5$CBB19/CBB10.3 Q5$CBB19/CBB16.3 Q5$CBB19/CBB22.3 Q5$CBB19/CBB28.3 Q5$CBB19/CBB34.3 Q5$CBB49/CBB4.3 Q5$CBB49/CBB10.3 Q5$CBB49/CBB16.3 Q5$CBB49/CBB22.3 Q5$CBB49/CBB28.3 Q5$CBB49/CBB34.3 Q8$CBB19/CBB4.3 Q8$CBB19/CBB10.3 Q8$CBB19/CBB16.3 Q8$CBB19/CBB22.3 Q8$CBB19/CBB28.3 Q8$CBB19/CBB34.3 Q8$CBB49/CBB4.3 Q8$CBB49/CBB10.3 Q8$CBB49/CBB16.3 Q8$CBB49/CBB22.3 Q8$CBB49/CBB28.3 Q8$CBB49/CBB34.3 U1$CBB16.13 U1$CBB16.14 | length 8548.9
  Top Layer w7.9: Q5$CBB49/CBB4.3@7648.6,7138.7 Q8$CBB49/CBB4.3@7648.6,7223.7 7674.9,7197.4 v1(7686,7197.4) ; Q5$CBB19/CBB4.3@7903.6,7138.7 Q8$CBB19/CBB4.3@7903.6,7223.7 ; Q5$CBB49/CBB10.3@8157.3,7138.7 Q8$CBB49/CBB10.3@8157.3,7223.7 8183.6,7197.4 v1(8194.7,7197.4) ; Q5$CBB19/CBB10.3@8412.3,7138.7 Q8$CBB19/CBB10.3@8412.3,7223.7 ; Q5$CBB49/CBB16.3@8666,7138.7 Q8$CBB49/CBB16.3@8666,7223.7 8692.3,7197.4 v1(8703.4,7197.4) ; Q5$CBB19/CBB16.3@8921,7138.7 Q8$CBB19/CBB16.3@8921,7223.7 ; Q5$CBB49/CBB22.3@9174.7,7138.7 Q8$CBB49/CBB22.3@9174.7,7223.7 9201,7197.4 v1(9212.1,7197.4) ; Q5$CBB19/CBB22.3@9429.7,7138.7 Q8$CBB19/CBB22.3@9429.7,7223.7 ; Q5$CBB49/CBB28.3@9683.4,7138.7 Q8$CBB49/CBB28.3@9683.4,7223.7 9709.7,7197.4 v1(9720.8,7197.4) ; Q5$CBB19/CBB28.3@9938.4,7138.7 Q8$CBB19/CBB28.3@9938.4,7223.7 ; Q5$CBB49/CBB34.3@10192.1,7138.7 Q8$CBB49/CBB34.3@10192.1,7223.7 10218.4,7197.4 v1(10229.5,7197.4) ; Q5$CBB19/CBB34.3@10447.1,7138.7 Q8$CBB19/CBB34.3@10447.1,7223.7
  Inner2 w7.9: v1(7326.2,7223.7) 7685.6,7223.7 ; v1(7686,7197.4) 7686,7223.4 7685.6,7223.7 ; v1(8194.7,7197.4) 8194.7,7223.4 8194.3,7223.7 ; v1(8703.4,7197.4) 8703.4,7223.3 8703,7223.7 v1(8903.6,7223.7) ; v1(9212.1,7197.4) 9212.1,7223.4 9211.7,7223.7 ; v1(9720.8,7197.4) 9720.8,7223.4 9720.4,7223.7 ; v1(10229.5,7197.4) 10229.5,7223.4 10229.1,7223.7 ; v1(10429.7,7223.7) 10229.1,7223.7 ; 7685.6,7223.7 v1(7886.2,7223.7) 8194.3,7223.7 ; 8194.3,7223.7 v1(8394.9,7223.7) v1(8903.6,7223.7) ; v1(8903.6,7223.7) 9211.7,7223.7 ; 9211.7,7223.7 v1(9412.3,7223.7) 9720.4,7223.7 ; 9720.4,7223.7 v1(9921,7223.7) 10229.1,7223.7
  Inner2 w23.6: v1(4933.5,7173.7) 6795.1,7173.7 6795.1,7176.3 6811.9,7193.1 6876.7,7193.1 6877.4,7192.4 6954,7192.4 6972.6,7173.7 7101.6,7173.7 7151.6,7223.7 v1(7326.2,7223.7)
  Inner4 w23.6: v1@4933.1,7173.7 4932.1,7173.7 4905.3,7200.6 4905.3,8306.9 4952.5,8354.1 v1(4957.1,8354.1)
  Bottom Layer w7.9: U1$CBB16.14@4880.3,8400.1 U1$CBB16.13@4880.3,8350.1 4953.1,8350.1 v1(4957.1,8354.1)
DAC2_D_ROW5: Q5$CBB19/CBB5.3 Q5$CBB19/CBB11.3 Q5$CBB19/CBB17.3 Q5$CBB19/CBB23.3 Q5$CBB19/CBB29.3 Q5$CBB19/CBB35.3 Q5$CBB49/CBB5.3 Q5$CBB49/CBB11.3 Q5$CBB49/CBB17.3 Q5$CBB49/CBB23.3 Q5$CBB49/CBB29.3 Q5$CBB49/CBB35.3 Q8$CBB19/CBB5.3 Q8$CBB19/CBB11.3 Q8$CBB19/CBB17.3 Q8$CBB19/CBB23.3 Q8$CBB19/CBB29.3 Q8$CBB19/CBB35.3 Q8$CBB49/CBB5.3 Q8$CBB49/CBB11.3 Q8$CBB49/CBB17.3 Q8$CBB49/CBB23.3 Q8$CBB49/CBB29.3 Q8$CBB49/CBB35.3 U2$CBB16.1 U2$CBB16.2 | length 7168.7
  Top Layer w7.9: Q5$CBB49/CBB5.3@7648.6,6618.7 Q8$CBB49/CBB5.3@7648.6,6703.7 7674.9,6677.4 v1(7686,6677.4) ; Q5$CBB19/CBB5.3@7903.6,6618.7 Q8$CBB19/CBB5.3@7903.6,6703.7 ; Q5$CBB49/CBB11.3@8157.3,6618.7 Q8$CBB49/CBB11.3@8157.3,6703.7 8183.6,6677.4 v1(8194.7,6677.4) ; Q5$CBB19/CBB11.3@8412.3,6618.7 Q8$CBB19/CBB11.3@8412.3,6703.7 ; Q5$CBB49/CBB17.3@8666,6618.7 Q8$CBB49/CBB17.3@8666,6703.7 8692.3,6677.4 v1(8703.4,6677.4) ; Q5$CBB19/CBB17.3@8921,6618.7 Q8$CBB19/CBB17.3@8921,6703.7 ; Q5$CBB49/CBB23.3@9174.7,6618.7 Q8$CBB49/CBB23.3@9174.7,6703.7 9201,6677.4 v1(9212.1,6677.4) ; Q5$CBB19/CBB23.3@9429.7,6618.7 Q8$CBB19/CBB23.3@9429.7,6703.7 ; Q5$CBB49/CBB29.3@9683.4,6618.7 Q8$CBB49/CBB29.3@9683.4,6703.7 9709.7,6677.4 v1(9720.8,6677.4) ; Q5$CBB19/CBB29.3@9938.4,6618.7 Q8$CBB19/CBB29.3@9938.4,6703.7 ; Q5$CBB49/CBB35.3@10192.1,6618.7 Q8$CBB49/CBB35.3@10192.1,6703.7 10218.4,6677.4 v1(10229.5,6677.4) ; Q5$CBB19/CBB35.3@10447.1,6618.7 Q8$CBB19/CBB35.3@10447.1,6703.7
  Inner2 w7.9: v1(7326.2,6703.7) 7685.6,6703.7 ; v1(7686,6677.4) 7686,6703.4 7685.6,6703.7 ; v1(8194.7,6677.4) 8194.7,6703.4 8194.3,6703.7 ; v1(8703.4,6677.4) 8703.4,6703.3 8703,6703.7 v1(8903.6,6703.7) ; v1(9212.1,6677.4) 9212.1,6703.4 9211.7,6703.7 ; v1(9720.8,6677.4) 9720.8,6703.4 9720.4,6703.7 ; v1(10229.5,6677.4) 10229.5,6703.4 10229.1,6703.7 ; v1(10429.7,6703.7) 10229.1,6703.7 ; 7685.6,6703.7 v1(7886.2,6703.7) 8194.3,6703.7 ; 8194.3,6703.7 v1(8394.9,6703.7) v1(8903.6,6703.7) ; v1(8903.6,6703.7) 9211.7,6703.7 ; 9211.7,6703.7 v1(9412.3,6703.7) 9720.4,6703.7 ; 9720.4,6703.7 v1(9921,6703.7) 10229.1,6703.7
  Inner2 w23.6: v3(5166.2,6708.7) 5604.7,6708.7 5606.3,6710.4 6887.4,6710.4 6889,6708.7 7002.1,6708.7 7007.1,6703.7 v1(7326.2,6703.7)
  Bottom Layer w7.9: U2$CBB16.2@5095.7,6535.8 U2$CBB16.1@5095.7,6585.8 ; U2$CBB16.1@5098.4,6589.1 5157.5,6589.1 5166.2,6597.8 v3(5166.2,6708.7)
DAC2_D_ROW6: Q5$CBB19/CBB6.3 Q5$CBB19/CBB12.3 Q5$CBB19/CBB18.3 Q5$CBB19/CBB24.3 Q5$CBB19/CBB30.3 Q5$CBB19/CBB36.3 Q5$CBB49/CBB6.3 Q5$CBB49/CBB12.3 Q5$CBB49/CBB18.3 Q5$CBB49/CBB24.3 Q5$CBB49/CBB30.3 Q5$CBB49/CBB36.3 Q8$CBB19/CBB6.3 Q8$CBB19/CBB12.3 Q8$CBB19/CBB18.3 Q8$CBB19/CBB24.3 Q8$CBB19/CBB30.3 Q8$CBB19/CBB36.3 Q8$CBB49/CBB6.3 Q8$CBB49/CBB12.3 Q8$CBB49/CBB18.3 Q8$CBB49/CBB24.3 Q8$CBB49/CBB30.3 Q8$CBB49/CBB36.3 U2$CBB16.6 U2$CBB16.7 | length 7413
  Top Layer w7.9: Q5$CBB49/CBB6.3@7648.6,5833.7 Q8$CBB49/CBB6.3@7648.6,5918.7 7674.9,5892.4 v1(7686,5892.4) ; Q5$CBB19/CBB6.3@7903.6,5833.7 Q8$CBB19/CBB6.3@7903.6,5918.7 ; Q5$CBB49/CBB12.3@8157.3,5833.7 Q8$CBB49/CBB12.3@8157.3,5918.7 8183.6,5892.4 v1(8194.7,5892.4) ; Q5$CBB19/CBB12.3@8412.3,5833.7 Q8$CBB19/CBB12.3@8412.3,5918.7 ; Q5$CBB49/CBB18.3@8666,5833.7 Q8$CBB49/CBB18.3@8666,5918.7 8692.3,5892.4 v1(8703.4,5892.4) ; Q5$CBB19/CBB18.3@8921,5833.7 Q8$CBB19/CBB18.3@8921,5918.7 ; Q5$CBB49/CBB24.3@9174.7,5833.7 Q8$CBB49/CBB24.3@9174.7,5918.7 9201,5892.4 v1(9212.1,5892.4) ; Q5$CBB19/CBB24.3@9429.7,5833.7 Q8$CBB19/CBB24.3@9429.7,5918.7 ; Q5$CBB49/CBB30.3@9683.4,5833.7 Q8$CBB49/CBB30.3@9683.4,5918.7 9709.7,5892.4 v1(9720.8,5892.4) ; Q5$CBB19/CBB30.3@9938.4,5833.7 Q8$CBB19/CBB30.3@9938.4,5918.7 ; Q5$CBB49/CBB36.3@10192.1,5833.7 Q8$CBB49/CBB36.3@10192.1,5918.7 10218.4,5892.4 v1(10229.5,5892.4) ; Q5$CBB19/CBB36.3@10447.1,5833.7 Q8$CBB19/CBB36.3@10447.1,5918.7
  Inner2 w7.9: v1(7326.2,5918.7) 7685.6,5918.7 ; v1(7686,5892.4) 7686,5918.4 7685.6,5918.7 ; v1(8194.7,5892.4) 8194.7,5918.4 8194.3,5918.7 ; v1(8703.4,5892.4) 8703.4,5918.3 8703,5918.7 v1(8903.6,5918.7) ; v1(9212.1,5892.4) 9212.1,5918.4 9211.7,5918.7 ; v1(9720.8,5892.4) 9720.8,5918.4 9720.4,5918.7 ; v1(10229.5,5892.4) 10229.5,5918.4 10229.1,5918.7 ; v1(10429.7,5918.7) 10229.1,5918.7 ; 7685.6,5918.7 v1(7886.2,5918.7) 8194.3,5918.7 ; 8194.3,5918.7 v1(8394.9,5918.7) v1(8903.6,5918.7) ; v1(8903.6,5918.7) 9211.7,5918.7 ; 9211.7,5918.7 v1(9412.3,5918.7) 9720.4,5918.7 ; 9720.4,5918.7 v1(9921,5918.7) 10229.1,5918.7
  Inner2 w23.6: v3(5107.1,5923.7) 5112.1,5918.7 v1(7326.2,5918.7)
  Inner4 w23.6: v3(5098.4,6218.7) 5098.4,5932.5 v3(5107.1,5923.7)
  Bottom Layer w7.9: U2$CBB16.7@5095.7,6285.8 U2$CBB16.6@5095.7,6335.8 ; v3(5098.4,6218.7) U2$CBB16.7@5098.4,6289.1
DAC2_D_ROW7: Q5$CBB9/CBB37.3 Q5$CBB9/CBB38.3 Q5$CBB9/CBB39.3 Q5$CBB9/CBB40.3 Q5$CBB9/CBB41.3 Q5$CBB9/CBB42.3 Q5$CBB49/CBB37.3 Q5$CBB49/CBB38.3 Q5$CBB49/CBB39.3 Q5$CBB49/CBB40.3 Q5$CBB49/CBB41.3 Q5$CBB49/CBB42.3 Q8$CBB9/CBB37.3 Q8$CBB9/CBB38.3 Q8$CBB9/CBB39.3 Q8$CBB9/CBB40.3 Q8$CBB9/CBB41.3 Q8$CBB9/CBB42.3 Q8$CBB49/CBB37.3 Q8$CBB49/CBB38.3 Q8$CBB49/CBB39.3 Q8$CBB49/CBB40.3 Q8$CBB49/CBB41.3 Q8$CBB49/CBB42.3 U2$CBB16.8 U2$CBB16.9 | length 12395.8
  Top Layer w7.9: Q5$CBB49/CBB37.3@7648.6,6098.7 Q8$CBB49/CBB37.3@7648.6,6183.7 7674.9,6157.4 v1(7686,6157.4) ; Q5$CBB9/CBB37.3@7648.6,8188.7 7676.2,8188.7 7686.2,8198.7 v1@7686.2,8258.7 ; Q8$CBB9/CBB37.3@7648.6,8273.7 7673.7,8273.7 v1(7688.7,8258.7) ; Q5$CBB49/CBB38.3@8157.3,6098.7 Q8$CBB49/CBB38.3@8157.3,6183.7 8183.6,6157.4 v1(8194.7,6157.4) ; Q5$CBB9/CBB38.3@8157.3,8188.7 8184.9,8188.7 8194.9,8198.7 v1@8194.9,8258.7 ; Q8$CBB9/CBB38.3@8157.3,8273.7 8182.4,8273.7 v1(8197.4,8258.7) ; Q5$CBB49/CBB39.3@8666,6098.7 Q8$CBB49/CBB39.3@8666,6183.7 8692.3,6157.4 v1(8703.4,6157.4) ; Q5$CBB9/CBB39.3@8666,8188.7 8693.6,8188.7 8703.6,8198.7 v1@8703.6,8258.7 ; Q8$CBB9/CBB39.3@8666,8273.7 8691.1,8273.7 v1(8706.1,8258.7) ; Q5$CBB49/CBB40.3@9174.7,6098.7 Q8$CBB49/CBB40.3@9174.7,6183.7 9201,6157.4 v1(9212.1,6157.4) ; Q5$CBB9/CBB40.3@9174.7,8188.7 9202.3,8188.7 9212.3,8198.7 v1@9212.3,8258.7 ; Q8$CBB9/CBB40.3@9174.7,8273.7 9199.8,8273.7 v1(9214.8,8258.7) ; Q5$CBB49/CBB41.3@9683.4,6098.7 Q8$CBB49/CBB41.3@9683.4,6183.7 9709.7,6157.4 v1(9720.8,6157.4) ; Q5$CBB9/CBB41.3@9683.4,8188.7 9711,8188.7 9721,8198.7 v1@9721,8258.7 ; Q8$CBB9/CBB41.3@9683.4,8273.7 9708.5,8273.7 v1(9723.5,8258.7) ; Q5$CBB49/CBB42.3@10192.1,6098.7 Q8$CBB49/CBB42.3@10192.1,6183.7 10218.4,6157.4 v1(10229.5,6157.4) ; Q5$CBB9/CBB42.3@10192.1,8188.7 10219.7,8188.7 10229.7,8198.7 v1@10229.7,8258.7 ; Q8$CBB9/CBB42.3@10192.1,8273.7 10217.2,8273.7 v1(10232.2,8258.7)
  Inner2 w7.9: v1(7326.2,6183.7) 7685.6,6183.7 ; v1(7326.2,8258.7) v1(7688.7,8258.7) v1(8197.4,8258.7) v1(8706.1,8258.7) v1(9214.8,8258.7) v1(9723.5,8258.7) v1(10232.2,8258.7) ; v1(7686,6157.4) 7686,6183.4 7685.6,6183.7 ; v1(8194.7,6157.4) 8194.7,6183.4 8194.3,6183.7 ; v1(8703.4,6157.4) 8703.4,6183.4 8703,6183.7 ; v1(9212.1,6157.4) 9212.1,6183.4 9211.7,6183.7 ; v1(9720.8,6157.4) 9720.8,6183.4 9720.4,6183.7 ; v1(10229.5,6157.4) 10229.5,6183.4 10229.1,6183.7 9720.4,6183.7 ; 7685.6,6183.7 8194.3,6183.7 ; 8194.3,6183.7 8703,6183.7 ; 8703,6183.7 9211.7,6183.7 ; 9211.7,6183.7 9720.4,6183.7
  Inner2 w23.6: v3@4872.1,6233.7 4907.1,6268.7 6927.1,6268.7 7012.1,6183.7 v1(7326.2,6183.7)
  Inner4 w23.6: v1(7326.2,6183.7) 7302.1,6183.7 7297.1,6188.7 7297.1,8253.7 7302.1,8258.7 v1(7326.2,8258.7)
  Bottom Layer w7.9: v3(4872.1,6233.8) 4872.1,6280.9 U2$CBB16.8@4877.6,6286.4 ; U2$CBB16.8@4877.6,6285.8 U2$CBB16.8@4877.6,6286.4 ; U2$CBB16.9@4877.6,6335.8 U2$CBB16.8@4877.6,6286.4 ; U2$CBB16.8@4880.3,6289.1 U2$CBB16.8@4877.6,6286.4
DAC2_D_ROW8: Q5$CBB49/CBB43.3 Q5$CBB49/CBB44.3 Q5$CBB49/CBB45.3 Q5$CBB49/CBB46.3 Q5$CBB49/CBB47.3 Q5$CBB49/CBB48.3 Q8$CBB49/CBB43.3 Q8$CBB49/CBB44.3 Q8$CBB49/CBB45.3 Q8$CBB49/CBB46.3 Q8$CBB49/CBB47.3 Q8$CBB49/CBB48.3 U2$CBB16.13 U2$CBB16.14 | length 7336.9
  Top Layer w7.9: Q5$CBB49/CBB43.3@7648.6,7403.7 Q8$CBB49/CBB43.3@7648.6,7488.7 7674.9,7462.4 v1(7686,7462.4) ; Q5$CBB49/CBB44.3@8157.3,7403.7 Q8$CBB49/CBB44.3@8157.3,7488.7 8183.6,7462.4 v1(8194.7,7462.4) ; Q5$CBB49/CBB45.3@8666,7403.7 Q8$CBB49/CBB45.3@8666,7488.7 8692.3,7462.4 v1(8703.4,7462.4) ; Q5$CBB49/CBB46.3@9174.7,7403.7 Q8$CBB49/CBB46.3@9174.7,7488.7 9201,7462.4 v1(9212.1,7462.4) ; Q5$CBB49/CBB47.3@9683.4,7403.7 Q8$CBB49/CBB47.3@9683.4,7488.7 9709.7,7462.4 v1(9720.8,7462.4) ; Q5$CBB49/CBB48.3@10192.1,7403.7 Q8$CBB49/CBB48.3@10192.1,7488.7 10218.4,7462.4 v1(10229.5,7462.4)
  Inner2 w7.9: v1(7326.2,7488.7) 7685.6,7488.7 ; v1(7686,7462.4) 7686,7488.4 7685.6,7488.7 ; v1(8194.7,7462.4) 8194.7,7488.4 8194.3,7488.7 ; v1(8703.4,7462.4) 8703.4,7488.4 8703,7488.7 ; v1(9212.1,7462.4) 9212.1,7488.4 9211.7,7488.7 ; v1(9720.8,7462.4) 9720.8,7488.4 9720.4,7488.7 ; v1(10229.5,7462.4) 10229.5,7488.4 10229.1,7488.7 9720.4,7488.7 ; 7685.6,7488.7 8194.3,7488.7 ; 8194.3,7488.7 8703,7488.7 ; 8703,7488.7 9211.7,7488.7 ; 9211.7,7488.7 9720.4,7488.7
  Inner2 w23.6: v3(4957.1,7468.7) 5017.5,7468.7 5021.5,7464.8 5042.8,7464.8 5057.8,7479.8 5631.5,7479.8 5646.5,7464.8 5667.8,7464.8 5682.8,7479.8 6261.4,7479.8 6276.4,7464.8 6297.7,7464.8 6312.7,7479.8 6891.3,7479.8 6906.3,7464.8 6927.6,7464.8 6951.5,7488.7 v1(7326.2,7488.7)
  Inner4 w23.6: v3(4957.1,7468.7) 4957.1,7270.1 4933.9,7246.9 4933.9,7223.3 4961.7,7195.6 4961.7,7133.2 4962.1,7132.7 4962.1,7013.7 4942.1,6993.7 4942.1,6802.1 4936.5,6796.5 4936.5,6775.2 4942.1,6769.5 4942.1,6630.8 v3@4970.2,6602.8
  Bottom Layer w7.9: U2$CBB16.13@4877.6,6535.8 U2$CBB16.14@4877.6,6585.8 ; U2$CBB16.14@4880.3,6589.1 4956.5,6589.1 v3@4970.2,6602.8
  other v3: 4970.6,6602.1
EN_P1: R53.1 R128.1 R140.1 U9.6 U12.6 U16.6 | length 1443.3
  Top Layer w11: U9.6@3636.3,6408.5 3666.7,6408.5 3669.4,6405.7 3719.6,6405.7 3741.1,6384.2 R53.1@3741.1,6375.4 ; U12.6@3636.3,6920.3 3666.7,6920.3 3669.4,6917.5 3729.5,6917.5 3741.1,6905.9 v1(3741.1,6887.2) ; U16.6@3636.3,7432.1 3666.7,7432.1 3669.4,7429.3 3719.6,7429.3 3741.1,7407.8 R140.1@3741.1,7399
  Inner4 w7.9: v1(3709,6403.9) 3711.8,6403.9 3713.6,6405.7 3713.6,6859.7 v1(3741.1,6887.2) 3741.1,7082.6 3729.7,7094 3729.7,7142.2 3713.6,7158.3 3713.6,7278.7 3689.5,7302.8 3689.5,7405.6 v1(3709.6,7425.6)
EN_P2: R124.1 U5.3 U7.3 U10.6 | length 1245.5
  Top Layer w7.9: U7.3@3452.6,7838.7 3500.6,7838.7 v1(3500.8,7838.9) ; v1(3872.2,8210.4) 3864.9,8203.1 R124.1@3864.9,8178.2 3864.9,8167.5 3877.1,8155.3 U10.6@3877.1,8135.5
  Inner2 w7.9: v1(3522.9,8174.3) 3836.1,8174.3 v1(3872.2,8210.4)
  Inner4 w4.7: v1(3872.2,8210.4) 3891.6,8229.8 3891.6,8595.2 3896.3,8599.9 v1(3896.3,8605.9)
  Inner4 w7.9: v1(3500.8,7838.9) 3500.8,7967.4 3522.9,7989.5 v1(3522.9,8174.3)
G+1_MAT(3): Q6$CBB49/CBB1.1 Q6$CBB49/CBB2.1 Q6$CBB49/CBB3.1 Q6$CBB49/CBB4.1 Q6$CBB49/CBB5.1 Q6$CBB49/CBB6.1 Q6$CBB49/CBB37.1 Q6$CBB49/CBB43.1 U1$CBB23.D13 | length 10915.9
  Top Layer w7.9: v1(7516.2,5833.9) 7516.2,5815.5 Q6$CBB49/CBB6.1@7523.6,5808.1 ; v1(7516.2,6098.9) 7516.2,6080.5 Q6$CBB49/CBB37.1@7523.6,6073.1 ; v1(7516.2,6618.9) 7516.2,6600.5 Q6$CBB49/CBB5.1@7523.6,6593.1 ; v1(7516.2,7138.9) 7516.2,7120.5 Q6$CBB49/CBB4.1@7523.6,7113.1 ; v1(7516.2,7403.9) 7516.2,7385.5 Q6$CBB49/CBB43.1@7523.6,7378.1 ; v1(7516.2,7923.9) 7516.2,7905.5 Q6$CBB49/CBB3.1@7523.6,7898.1 ; v1(7516.2,8708.9) 7516.2,8690.5 Q6$CBB49/CBB2.1@7523.6,8683.1 ; v1(7516.2,9228.9) 7516.2,9210.5 Q6$CBB49/CBB1.1@7523.6,9203.1
  Inner4 w4.7: v2(4144.6,5814.9) 4151.3,5814.9 4165.4,5829.1 4185.5,5829.1 4191.5,5835.1 4191.5,5859.2 4185.8,5864.8 4185.8,5910.7 4183.1,5913.4 4183.1,5979.7 4128,6034.8 4128,7195 4208.8,7275.8 4208.8,8958.3 4255.6,9005 4255.6,9322.5 4351.5,9418.5 7470.1,9418.5 v1(7489.9,9398.7)
  Inner4 w7.9: v1(7489.9,9398.7) 7489.9,9231.2 ; v1(7516.2,5833.9) 7492.1,5833.9 7489.9,5836.2 7489.9,6101.2 ; v1(7516.2,6098.9) 7492.1,6098.9 7489.9,6101.2 ; v1(7516.2,6618.9) 7492.1,6618.9 7489.9,6621.2 ; v1(7516.2,7138.9) 7492.1,7138.9 7489.9,7141.2 ; v1(7516.2,7403.9) 7492.1,7403.9 7489.9,7406.2 ; v1(7516.2,7923.9) 7492.1,7923.9 7489.9,7926.2 ; v1(7516.2,8708.9) 7492.1,8708.9 7489.9,8711.2 ; v1(7516.2,9228.9) 7492.1,9228.9 7489.9,9231.2 ; 7489.9,6101.2 7489.9,6621.2 ; 7489.9,6621.2 7489.9,7141.2 ; 7489.9,7141.2 7489.9,7406.2 ; 7489.9,7406.2 7489.9,7926.2 ; 7489.9,7926.2 7489.9,8711.2 ; 7489.9,8711.2 7489.9,9231.2
G+1_MAT(8): Q6$CBB9/CBB1.1 Q6$CBB9/CBB2.1 Q6$CBB9/CBB3.1 Q6$CBB9/CBB4.1 Q6$CBB9/CBB5.1 Q6$CBB9/CBB6.1 Q6$CBB9/CBB37.1 U1$CBB23.C14 | length 10875.6
  Inner4 w4.7: v2(4176.1,5846.4) 4176.1,5906.7 4173.4,5909.4 4173.4,5917.4 4118.3,5972.6 4118.3,7199 4199.1,7279.9 4199.1,8962.3 4245.9,9009.1 4245.9,9326.6 4347.5,9428.2 7511.7,9428.2 v1(7541.2,9398.7)
  Inner4 w7.9: v1(7523.6,5553.1) 7541,5553.1 7541.2,5553 7541.2,6338 ; v1(7523.6,6338.1) 7541,6338.1 7541.2,6338 ; v1(7523.6,6858.1) 7541,6858.1 7541.2,6858 ; v1(7523.6,7643.1) 7541,7643.1 7541.2,7643 ; v1(7523.6,8163.1) 7541,8163.1 7541.2,8163 ; v1(7523.6,8428.1) 7541,8428.1 7541.2,8428 ; v1(7523.6,8948.1) 7541,8948.1 7541.2,8948 ; v1(7541.2,9398.7) 7541.2,8948 ; 7541.2,6338 7541.2,6858 ; 7541.2,6858 7541.2,7643 ; 7541.2,7643 7541.2,8163 ; 7541.2,8163 7541.2,8428 ; 7541.2,8428 7541.2,8948
G+1_MAT(33): Q6$CBB19/CBB1.1 Q6$CBB19/CBB2.1 Q6$CBB19/CBB3.1 Q6$CBB19/CBB4.1 Q6$CBB19/CBB5.1 Q6$CBB19/CBB6.1 U1$CBB23.C13 | length 10984.2
  Top Layer w7.9: Q6$CBB19/CBB6.1@7778.6,5808.1 7778.6,5826.1 v1@7781.2,5828.7 ; Q6$CBB19/CBB5.1@7778.6,6593.1 7778.6,6611.1 v1@7781.2,6613.7 ; Q6$CBB19/CBB4.1@7778.6,7113.1 7778.6,7131.1 v1@7781.2,7133.7 ; Q6$CBB19/CBB3.1@7778.6,7898.1 7778.6,7916.1 v1@7781.2,7918.7 ; Q6$CBB19/CBB2.1@7778.6,8683.1 7778.6,8701.1 v1@7781.2,8703.7 ; Q6$CBB19/CBB1.1@7778.6,9203.1 7778.6,9221.1 v1@7781.2,9223.7
  Inner4 w4.7: v2(4144.6,5846.4) 4144.6,5873.9 4129.3,5889.3 4129.3,5932.1 4098.8,5962.5 4098.8,7207.1 4179.6,7287.9 4179.6,8970.3 4226.4,9017.1 4226.4,9334.6 4339.5,9447.7 7747.2,9447.7 v1(7796.2,9398.7)
  Inner4 w7.9: v1(7782,5829.5) 7782.8,5828.7 7796.2,5828.7 7796.2,6613.7 ; v1(7782,6614.5) 7782.8,6613.7 7796.2,6613.7 ; v1(7782,7134.5) 7782.8,7133.7 7796.2,7133.7 ; v1(7782,7919.5) 7782.8,7918.7 7796.2,7918.7 ; v1(7782,8704.5) 7782.8,8703.7 7796.2,8703.7 ; v1(7782,9224.5) 7782.8,9223.7 7796.2,9223.7 ; v1(7796.2,9398.7) 7796.2,9223.7 ; 7796.2,6613.7 7796.2,7133.7 ; 7796.2,7133.7 7796.2,7918.7 ; 7796.2,7918.7 7796.2,8703.7 ; 7796.2,8703.7 7796.2,9223.7
G+2_MAT(3): Q6$CBB49/CBB7.1 Q6$CBB49/CBB8.1 Q6$CBB49/CBB9.1 Q6$CBB49/CBB10.1 Q6$CBB49/CBB11.1 Q6$CBB49/CBB12.1 Q6$CBB49/CBB38.1 Q6$CBB49/CBB44.1 U1$CBB23.F12 | length 11565.1
  Top Layer w7.9: v1(8024.9,5833.9) 8024.9,5815.5 Q6$CBB49/CBB12.1@8032.3,5808.1 ; v1(8024.9,6098.9) 8024.9,6080.5 Q6$CBB49/CBB38.1@8032.3,6073.1 ; v1(8024.9,6618.9) 8024.9,6600.5 Q6$CBB49/CBB11.1@8032.3,6593.1 ; v1(8024.9,7138.9) 8024.9,7120.5 Q6$CBB49/CBB10.1@8032.3,7113.1 ; v1(8024.9,7403.9) 8024.9,7385.5 Q6$CBB49/CBB44.1@8032.3,7378.1 ; v1(8024.9,7923.9) 8024.9,7905.5 Q6$CBB49/CBB9.1@8032.3,7898.1 ; v1(8024.9,8708.9) 8024.9,8690.5 Q6$CBB49/CBB8.1@8032.3,8683.1 ; v1(8024.9,9228.9) 8024.9,9210.5 Q6$CBB49/CBB7.1@8032.3,9203.1
  Inner4 w4.7: v2(4113.1,5751.9) 4097.1,5767.9 4097.1,5855.2 4069.6,5882.6 4069.6,7219.2 4150.5,7300 4150.5,8982.4 4197.2,9029.2 4197.2,9346.7 4327.4,9476.9 7920.5,9476.9 v1(7998.6,9398.7)
  Inner4 w7.9: v1(7998.6,9398.7) 7998.6,9231.2 ; v1(8024.9,5833.9) 8000.8,5833.9 7998.6,5836.2 7998.6,6101.2 ; v1(8024.9,6098.9) 8000.8,6098.9 7998.6,6101.2 ; v1(8024.9,6618.9) 8000.8,6618.9 7998.6,6621.2 ; v1(8024.9,7138.9) 8000.8,7138.9 7998.6,7141.2 ; v1(8024.9,7403.9) 8000.8,7403.9 7998.6,7406.2 ; v1(8024.9,7923.9) 8000.8,7923.9 7998.6,7926.2 ; v1(8024.9,8708.9) 8000.8,8708.9 7998.6,8711.2 ; v1(8024.9,9228.9) 8000.8,9228.9 7998.6,9231.2 ; 7998.6,6101.2 7998.6,6621.2 ; 7998.6,6621.2 7998.6,7141.2 ; 7998.6,7141.2 7998.6,7406.2 ; 7998.6,7406.2 7998.6,7926.2 ; 7998.6,7926.2 7998.6,8711.2 ; 7998.6,8711.2 7998.6,9231.2
G+2_MAT(8): Q6$CBB9/CBB7.1 Q6$CBB9/CBB8.1 Q6$CBB9/CBB9.1 Q6$CBB9/CBB10.1 Q6$CBB9/CBB11.1 Q6$CBB9/CBB12.1 Q6$CBB9/CBB38.1 U1$CBB23.C11 | length 11490.4
  Inner4 w4.7: v2(4081.6,5846.4) 4059.9,5868.1 4059.9,7223.2 4140.7,7304 4140.7,8986.5 4187.5,9033.2 4187.5,9350.7 4323.3,9486.6 7962,9486.6 v1(8049.9,9398.7)
  Inner4 w7.9: v1(8032.3,5553.1) 8049.7,5553.1 8049.9,5553 8049.9,6338 ; v1(8032.3,6338.1) 8049.7,6338.1 8049.9,6338 ; v1(8032.3,6858.1) 8049.7,6858.1 8049.9,6858 ; v1(8032.3,7643.1) 8049.7,7643.1 8049.9,7643 ; v1(8032.3,8163.1) 8049.7,8163.1 8049.9,8163 ; v1(8032.3,8428.1) 8049.7,8428.1 8049.9,8428 ; v1(8032.3,8948.1) 8049.7,8948.1 8049.9,8948 ; v1(8049.9,9398.7) 8049.9,8948 ; 8049.9,6338 8049.9,6858 ; 8049.9,6858 8049.9,7643 ; 8049.9,7643 8049.9,8163 ; 8049.9,8163 8049.9,8428 ; 8049.9,8428 8049.9,8948
G+2_MAT(33): Q6$CBB19/CBB7.1 Q6$CBB19/CBB8.1 Q6$CBB19/CBB9.1 Q6$CBB19/CBB10.1 Q6$CBB19/CBB11.1 Q6$CBB19/CBB12.1 U1$CBB23.D11 | length 11699.2
  Top Layer w7.9: Q6$CBB19/CBB12.1@8287.3,5808.1 8287.3,5826.1 v1@8289.9,5828.7 ; Q6$CBB19/CBB11.1@8287.3,6593.1 8287.3,6611.1 v1@8289.9,6613.7 ; Q6$CBB19/CBB10.1@8287.3,7113.1 8287.3,7131.1 v1@8289.9,7133.7 ; Q6$CBB19/CBB9.1@8287.3,7898.1 8287.3,7916.1 v1@8289.9,7918.7 ; Q6$CBB19/CBB8.1@8287.3,8683.1 8287.3,8701.1 v1@8289.9,8703.7 ; Q6$CBB19/CBB7.1@8287.3,9203.1 8287.3,9221.1 v1@8289.9,9223.7
  Inner4 w4.7: v2(4081.6,5814.9) 4047.6,5814.9 4042.9,5819.6 4042.9,5833.5 4035.9,5840.5 4035.9,5852.3 4040.5,5856.9 4040.5,7231.2 4121.3,7312.1 4121.3,8994.5 4168.1,9041.3 4168.1,9358.8 4315.3,9506 8252.6,9506 8304.9,9453.8 v1(8304.9,9398.7)
  Inner4 w7.9: v1(8290.7,5829.5) 8291.5,5828.7 8304.9,5828.7 8304.9,6613.7 ; v1(8290.7,6614.5) 8291.5,6613.7 8304.9,6613.7 ; v1(8290.7,7134.5) 8291.5,7133.7 8304.9,7133.7 ; v1(8290.7,7919.5) 8291.5,7918.7 8304.9,7918.7 ; v1(8290.7,8704.5) 8291.5,8703.7 8304.9,8703.7 ; v1(8290.7,9224.5) 8291.5,9223.7 8304.9,9223.7 ; v1(8304.9,9398.7) 8304.9,9223.7 ; 8304.9,6613.7 8304.9,7133.7 ; 8304.9,7133.7 8304.9,7918.7 ; 8304.9,7918.7 8304.9,8703.7 ; 8304.9,8703.7 8304.9,9223.7
G+3_MAT(3): Q6$CBB49/CBB13.1 Q6$CBB49/CBB14.1 Q6$CBB49/CBB15.1 Q6$CBB49/CBB16.1 Q6$CBB49/CBB17.1 Q6$CBB49/CBB18.1 Q6$CBB49/CBB39.1 Q6$CBB49/CBB45.1 U1$CBB23.F5 | length 12309
  Top Layer w7.9: v1(8533.6,5833.9) 8533.6,5815.5 Q6$CBB49/CBB18.1@8541,5808.1 ; v1(8533.6,6098.9) 8533.6,6080.5 Q6$CBB49/CBB39.1@8541,6073.1 ; v1(8533.6,6618.9) 8533.6,6600.5 Q6$CBB49/CBB17.1@8541,6593.1 ; v1(8533.6,7138.9) 8533.6,7120.5 Q6$CBB49/CBB16.1@8541,7113.1 ; v1(8533.6,7403.9) 8533.6,7385.5 Q6$CBB49/CBB45.1@8541,7378.1 ; v1(8533.6,7923.9) 8533.6,7905.5 Q6$CBB49/CBB15.1@8541,7898.1 ; v1(8533.6,8708.9) 8533.6,8690.5 Q6$CBB49/CBB14.1@8541,8683.1 ; v1(8533.6,9228.9) 8533.6,9210.5 Q6$CBB49/CBB13.1@8541,9203.1
  Inner4 w4.7: v2(3892.6,5751.9) 3909.5,5768.8 3934.5,5768.8 3978.7,5813 3978.7,5867.2 3936.5,5909.4 3936.5,6067.7 3912.4,6091.8 3912.4,7117.5 3912.7,7117.8 3912.7,7144.8 4092.1,7324.2 4092.1,9006.6 4138.9,9053.4 4138.9,9370.9 4303.2,9535.2 8269.3,9535.2 8269.3,9538.3 8278.8,9547.8 8292.3,9547.8 8301.8,9538.3 8301.8,9535.2 8370.8,9535.2 v1(8507.3,9398.7)
  Inner4 w7.9: v1(8507.3,9398.7) 8507.3,9231.1 ; v1(8533.6,5833.9) 8509.5,5833.9 8507.3,5836.1 8507.3,6101.2 ; v1(8533.6,6098.9) 8509.5,6098.9 8507.3,6101.2 ; v1(8533.6,6618.9) 8509.5,6618.9 8507.3,6621.1 ; v1(8533.6,7138.9) 8509.5,7138.9 8507.3,7141.1 ; v1(8533.6,7403.9) 8509.5,7403.9 8507.3,7406.2 ; v1(8533.6,7923.9) 8509.5,7923.9 8507.3,7926.1 ; v1(8533.6,8708.9) 8509.5,8708.9 8507.3,8711.1 ; v1(8533.6,9228.9) 8509.5,9228.9 8507.3,9231.1 ; 8507.3,6101.2 8507.3,6621.1 ; 8507.3,6621.1 8507.3,7141.1 ; 8507.3,7141.1 8507.3,7406.2 ; 8507.3,7406.2 8507.3,7926.1 ; 8507.3,7926.1 8507.3,8711.1 ; 8507.3,8711.1 8507.3,9231.1
G+3_MAT(8): Q6$CBB9/CBB13.1 Q6$CBB9/CBB14.1 Q6$CBB9/CBB15.1 Q6$CBB9/CBB16.1 Q6$CBB9/CBB17.1 Q6$CBB9/CBB18.1 Q6$CBB9/CBB39.1 U1$CBB23.E6 | length 12281.6
  Inner4 w4.7: v2(3924.1,5783.4) 3942.2,5801.5 3942.2,5820.5 3954.8,5833 3961.2,5833 3969,5840.9 3969,5852 3968.6,5852.4 3968.6,5863.2 3926.8,5905 3926.8,6063.7 3902.7,6087.8 3902.7,7121.5 3903,7121.8 3903,7148.8 4082.4,7328.2 4082.4,9010.6 4129.2,9057.4 4129.2,9374.9 4299.2,9544.9 8262.2,9544.9 8274.8,9557.5 8296.3,9557.5 8308.9,9544.9 8422.8,9544.9 8558.6,9409.1 v1(8558.6,9398.7)
  Inner4 w7.9: v1(8541,5553.1) 8558.4,5553.1 8558.6,5552.9 8558.6,6337.9 ; v1(8541,6338.1) 8558.4,6338.1 8558.6,6337.9 ; v1(8541,6858.1) 8558.4,6858.1 8558.6,6857.9 ; v1(8541,7643.1) 8558.4,7643.1 8558.6,7642.9 ; v1(8541,8163.1) 8558.4,8163.1 8558.6,8162.9 ; v1(8541,8428.1) 8558.4,8428.1 8558.6,8427.9 ; v1(8541,8948.1) 8558.4,8948.1 8558.6,8947.9 ; v1(8558.6,9398.7) 8558.6,8947.9 ; 8558.6,6337.9 8558.6,6857.9 ; 8558.6,6857.9 8558.6,7642.9 ; 8558.6,7642.9 8558.6,8162.9 ; 8558.6,8162.9 8558.6,8427.9 ; 8558.6,8427.9 8558.6,8947.9
G+3_MAT(33): Q6$CBB19/CBB13.1 Q6$CBB19/CBB14.1 Q6$CBB19/CBB15.1 Q6$CBB19/CBB16.1 Q6$CBB19/CBB17.1 Q6$CBB19/CBB18.1 U1$CBB23.C6 | length 12293.1
  Top Layer w7.9: Q6$CBB19/CBB18.1@8796,5808.1 8796,5826.1 v1@8798.6,5828.7 ; Q6$CBB19/CBB17.1@8796,6593.1 8796,6611.1 v1@8798.6,6613.7 ; Q6$CBB19/CBB16.1@8796,7113.1 8796,7131.1 v1@8798.6,7133.7 ; Q6$CBB19/CBB15.1@8796,7898.1 8796,7916.1 v1@8798.6,7918.7 ; Q6$CBB19/CBB14.1@8796,8683.1 8796,8701.1 v1@8798.6,8703.7 ; Q6$CBB19/CBB13.1@8796,9203.1 8796,9221.1 v1@8798.6,9223.7
  Inner4 w4.7: v2(3924.1,5846.4) 3924.1,5867.5 3907.3,5884.3 3907.3,5932.5 3882.7,5957.2 3882.7,7129 3883.5,7129.9 3883.5,7156.8 4063,7336.2 4063,9018.7 4109.7,9065.5 4109.7,9383 4291.1,9564.4 8254.1,9564.4 8266.7,9577 8304.4,9577 8317,9564.4 8648,9564.4 v1(8813.6,9398.7)
  Inner4 w7.9: v1(8799.4,5829.5) 8800.2,5828.7 8813.6,5828.7 8813.6,6613.7 ; v1(8799.4,6614.5) 8800.2,6613.7 8813.6,6613.7 ; v1(8799.4,7134.5) 8800.2,7133.7 8813.6,7133.7 ; v1(8799.4,7919.5) 8800.2,7918.7 8813.6,7918.7 ; v1(8799.4,8704.5) 8800.2,8703.7 8813.6,8703.7 ; v1(8799.4,9224.5) 8800.2,9223.7 8813.6,9223.7 ; v1(8813.6,9398.7) 8813.6,9223.7 ; 8813.6,6613.7 8813.6,7133.7 ; 8813.6,7133.7 8813.6,7918.7 ; 8813.6,7918.7 8813.6,8703.7 ; 8813.6,8703.7 8813.6,9223.7
G+4_MAT(3): Q6$CBB49/CBB19.1 Q6$CBB49/CBB20.1 Q6$CBB49/CBB21.1 Q6$CBB49/CBB22.1 Q6$CBB49/CBB23.1 Q6$CBB49/CBB24.1 Q6$CBB49/CBB40.1 Q6$CBB49/CBB46.1 U1$CBB23.E4 | length 12960.5
  Top Layer w7.9: v1(9042.3,5833.9) 9042.3,5815.5 Q6$CBB49/CBB24.1@9049.7,5808.1 ; v1(9042.3,6098.9) 9042.3,6080.5 Q6$CBB49/CBB40.1@9049.7,6073.1 ; v1(9042.3,6618.9) 9042.3,6600.5 Q6$CBB49/CBB23.1@9049.7,6593.1 ; v1(9042.3,7138.9) 9042.3,7120.5 Q6$CBB49/CBB22.1@9049.7,7113.1 ; v1(9042.3,7403.9) 9042.3,7385.5 Q6$CBB49/CBB46.1@9049.7,7378.1 ; v1(9042.3,7923.9) 9042.3,7905.5 Q6$CBB49/CBB21.1@9049.7,7898.1 ; v1(9042.3,8708.9) 9042.3,8690.5 Q6$CBB49/CBB20.1@9049.7,8683.1 ; v1(9042.3,9228.9) 9042.3,9210.5 Q6$CBB49/CBB19.1@9049.7,9203.1
  Inner4 w4.7: v2(3861.1,5783.4) 3876.3,5798.5 3876.3,5827 3886.3,5837.1 3886.3,5857.2 3854.5,5889 3854.5,5889.6 3853.5,5890.6 3853.5,7141.1 3854.4,7142 3854.4,7168.9 4033.8,7348.3 4033.8,9030.8 4080.6,9077.5 4080.6,9395.1 4279,9593.5 8242.1,9593.5 8254.7,9606.1 8316.4,9606.1 8329,9593.5 9009.5,9593.5 9016,9587.1 v1(9016,9398.7)
  Inner4 w7.9: v1(9016,9398.7) 9016,9231.2 ; v1(9042.3,5833.9) 9018.2,5833.9 9016,5836.2 9016,6101.2 ; v1(9042.3,6098.9) 9018.2,6098.9 9016,6101.2 ; v1(9042.3,6618.9) 9018.2,6618.9 9016,6621.2 ; v1(9042.3,7138.9) 9018.2,7138.9 9016,7141.2 ; v1(9042.3,7403.9) 9018.2,7403.9 9016,7406.2 ; v1(9042.3,7923.9) 9018.2,7923.9 9016,7926.2 ; v1(9042.3,8708.9) 9018.2,8708.9 9016,8711.2 ; v1(9042.3,9228.9) 9018.2,9228.9 9016,9231.2 ; 9016,6101.2 9016,6621.2 ; 9016,6621.2 9016,7141.2 ; 9016,7141.2 9016,7406.2 ; 9016,7406.2 9016,7926.2 ; 9016,7926.2 9016,8711.2 ; 9016,8711.2 9016,9231.2
G+4_MAT(8): Q6$CBB9/CBB19.1 Q6$CBB9/CBB20.1 Q6$CBB9/CBB21.1 Q6$CBB9/CBB22.1 Q6$CBB9/CBB23.1 Q6$CBB9/CBB24.1 Q6$CBB9/CBB40.1 U1$CBB23.D4 | length 13124.4
  Inner4 w4.7: v2(3861.1,5814.9) 3861.1,5826 3876.3,5841.1 3876.3,5854.4 3851.4,5879.3 3850.5,5879.3 3844.8,5884.9 3844.8,5885.6 3843.8,5886.5 3843.8,7145.1 3844.6,7146 3844.6,7172.9 4024.1,7352.4 4024.1,9034.8 4070.8,9081.6 4070.8,9399.1 4275,9603.3 8238,9603.3 8250.6,9615.9 8320.5,9615.9 8333.1,9603.3 9061.1,9603.3 9067.3,9597.1 v1(9067.3,9398.7)
  Inner4 w7.9: v1(9049.7,5553.1) 9067.1,5553.1 9067.3,5553 ; v1(9049.7,6338.1) 9067.1,6338.1 9067.3,6338 ; v1(9049.7,6858.1) 9067.1,6858.1 9067.3,6858 ; v1(9049.7,7643.1) 9067.1,7643.1 9067.3,7643 ; v1(9049.7,8163.1) 9067.1,8163.1 9067.3,8163 ; v1(9049.7,8428.1) 9067.1,8428.1 9067.3,8428 ; v1(9049.7,8948.1) 9067.1,8948.1 9067.3,8948 ; 9067.3,5388.7 9067.3,5553 ; v1(9067.3,9398.7) 9067.3,8948 ; 9067.3,5553 9067.3,6338 ; 9067.3,6338 9067.3,6858 ; 9067.3,6858 9067.3,7643 ; 9067.3,7643 9067.3,8163 ; 9067.3,8163 9067.3,8428 ; 9067.3,8428 9067.3,8948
